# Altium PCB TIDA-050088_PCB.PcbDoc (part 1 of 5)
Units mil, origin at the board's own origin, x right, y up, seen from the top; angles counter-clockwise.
Board outline 8500 x 7000 mil, 8 copper layers (Top Layer, Layer 1 - GND, Signal Layer 2, Layer 3 - GND, Layer 4 - Power, Signal Layer 5, Layer 6 - GND, Bottom Layer), stack 61.6 mil thick; 537 components, 169 nets, 1427 pads, 1411 vias.
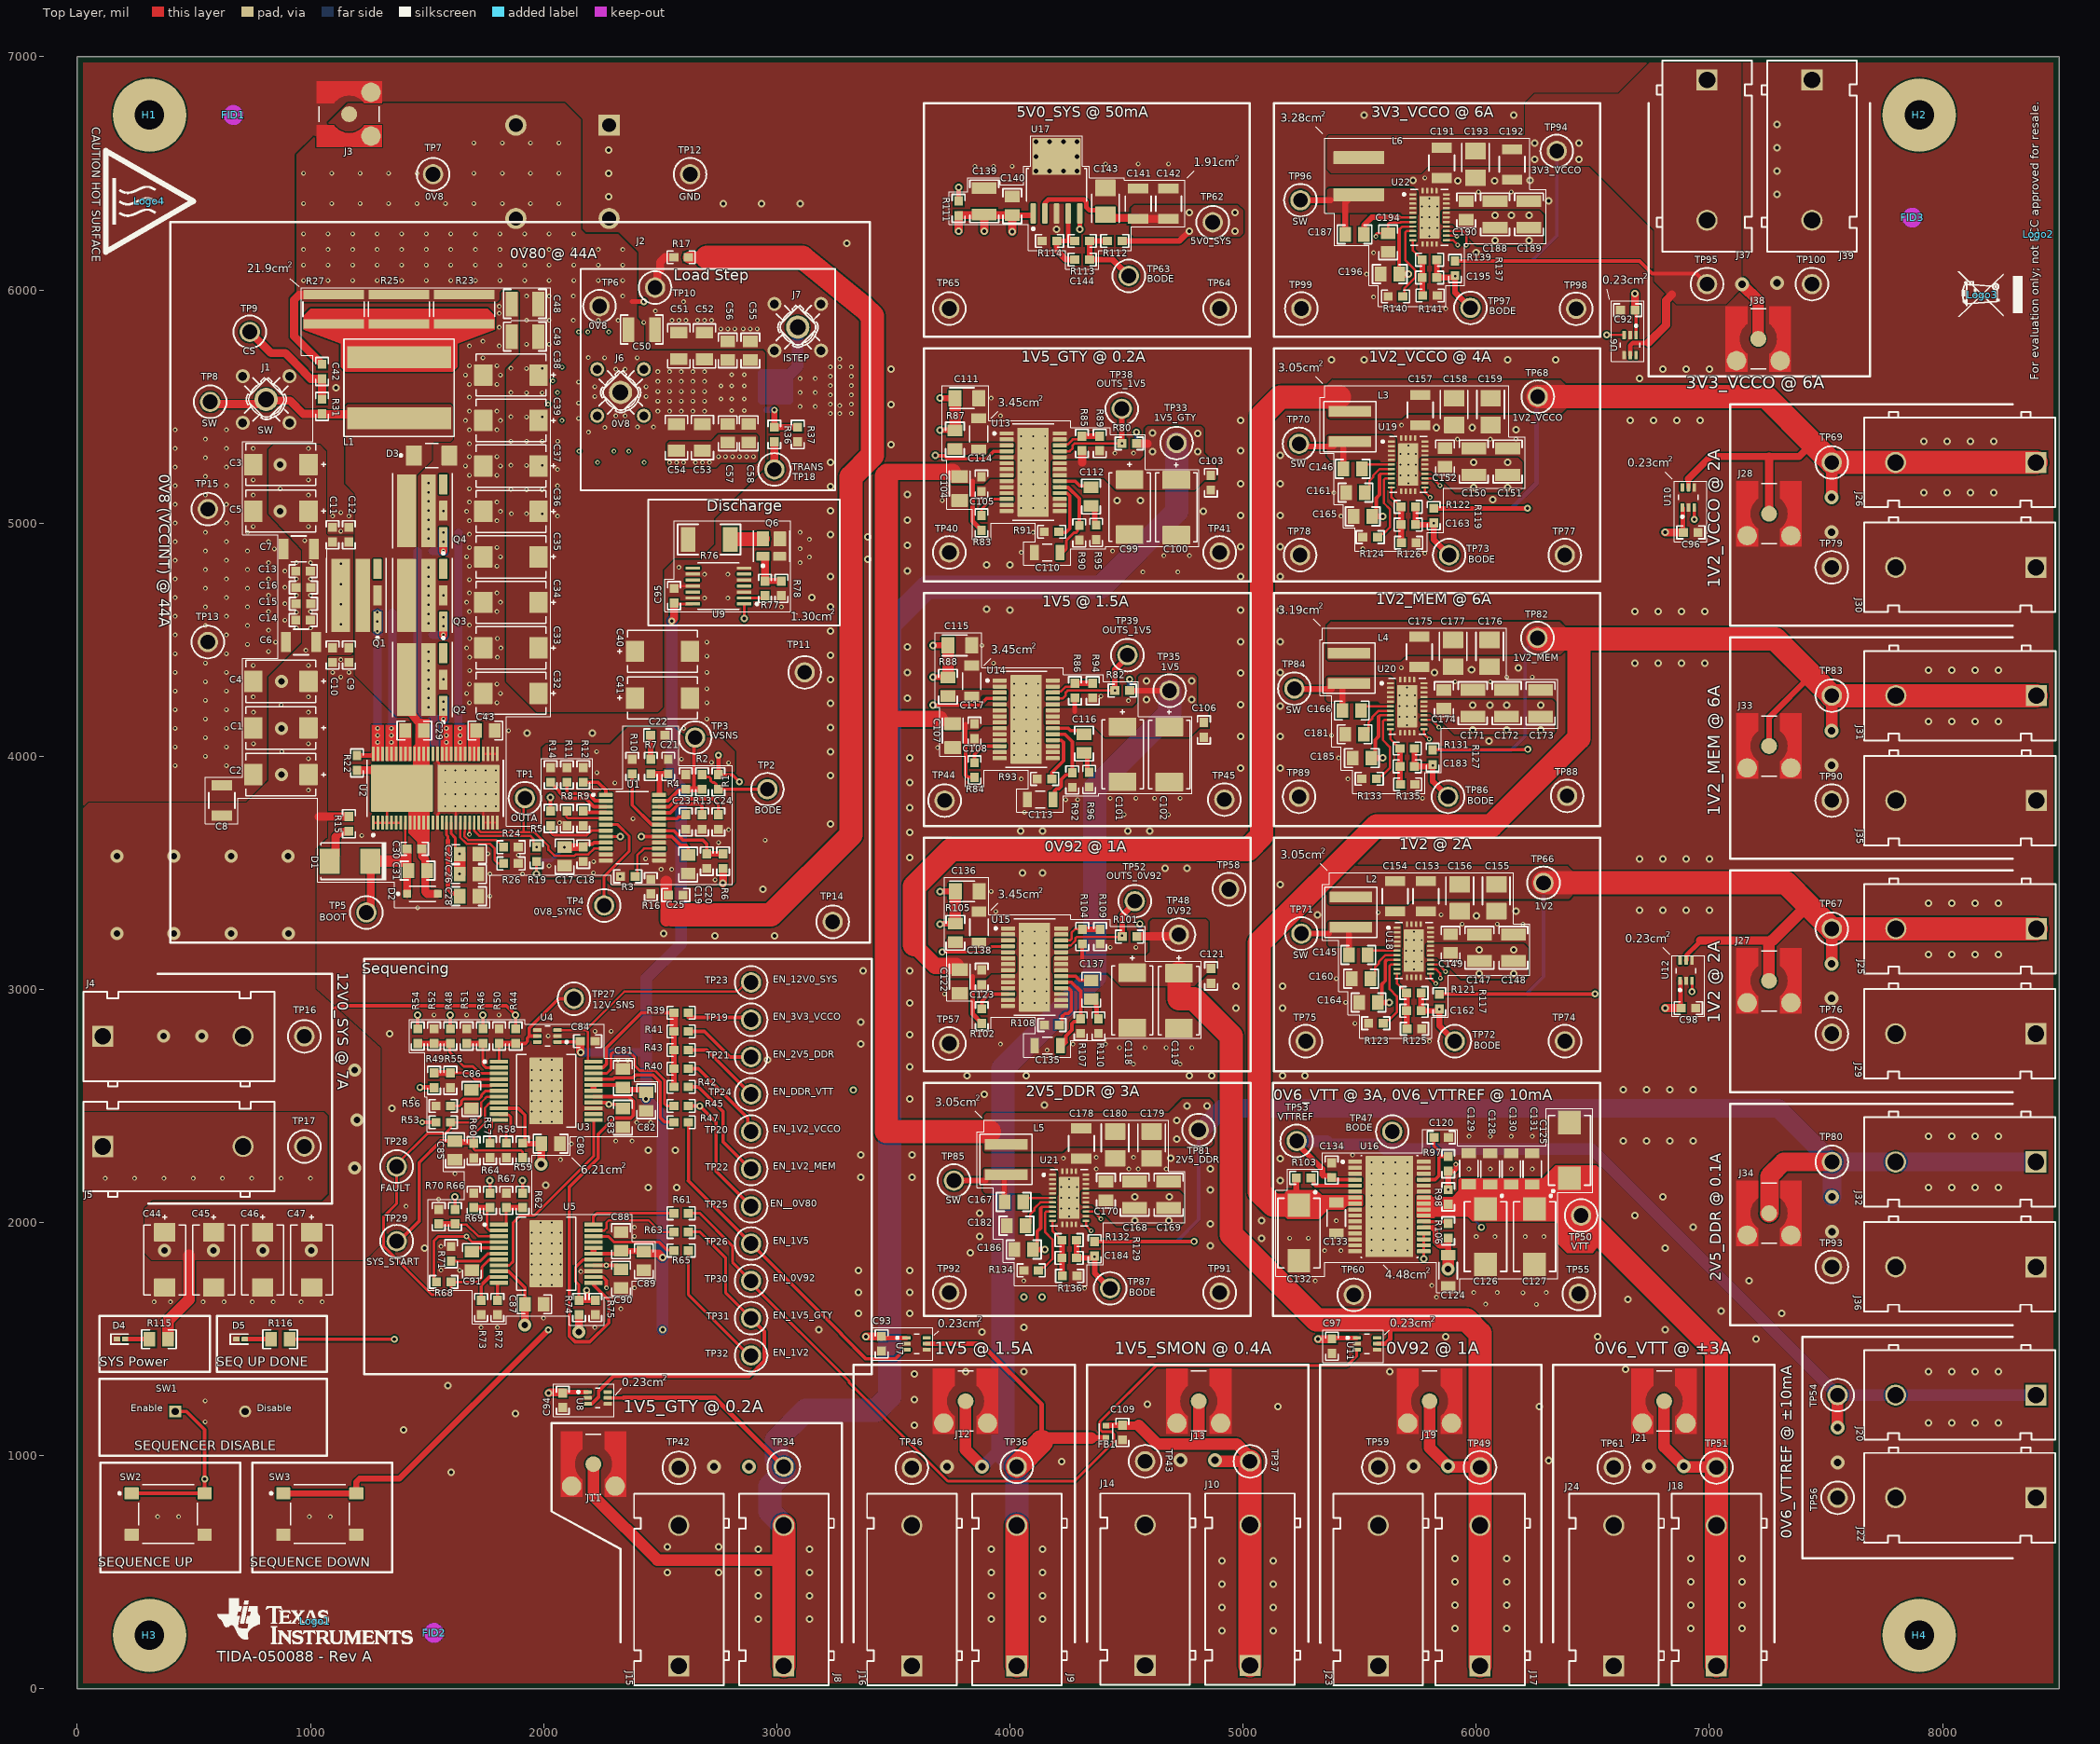
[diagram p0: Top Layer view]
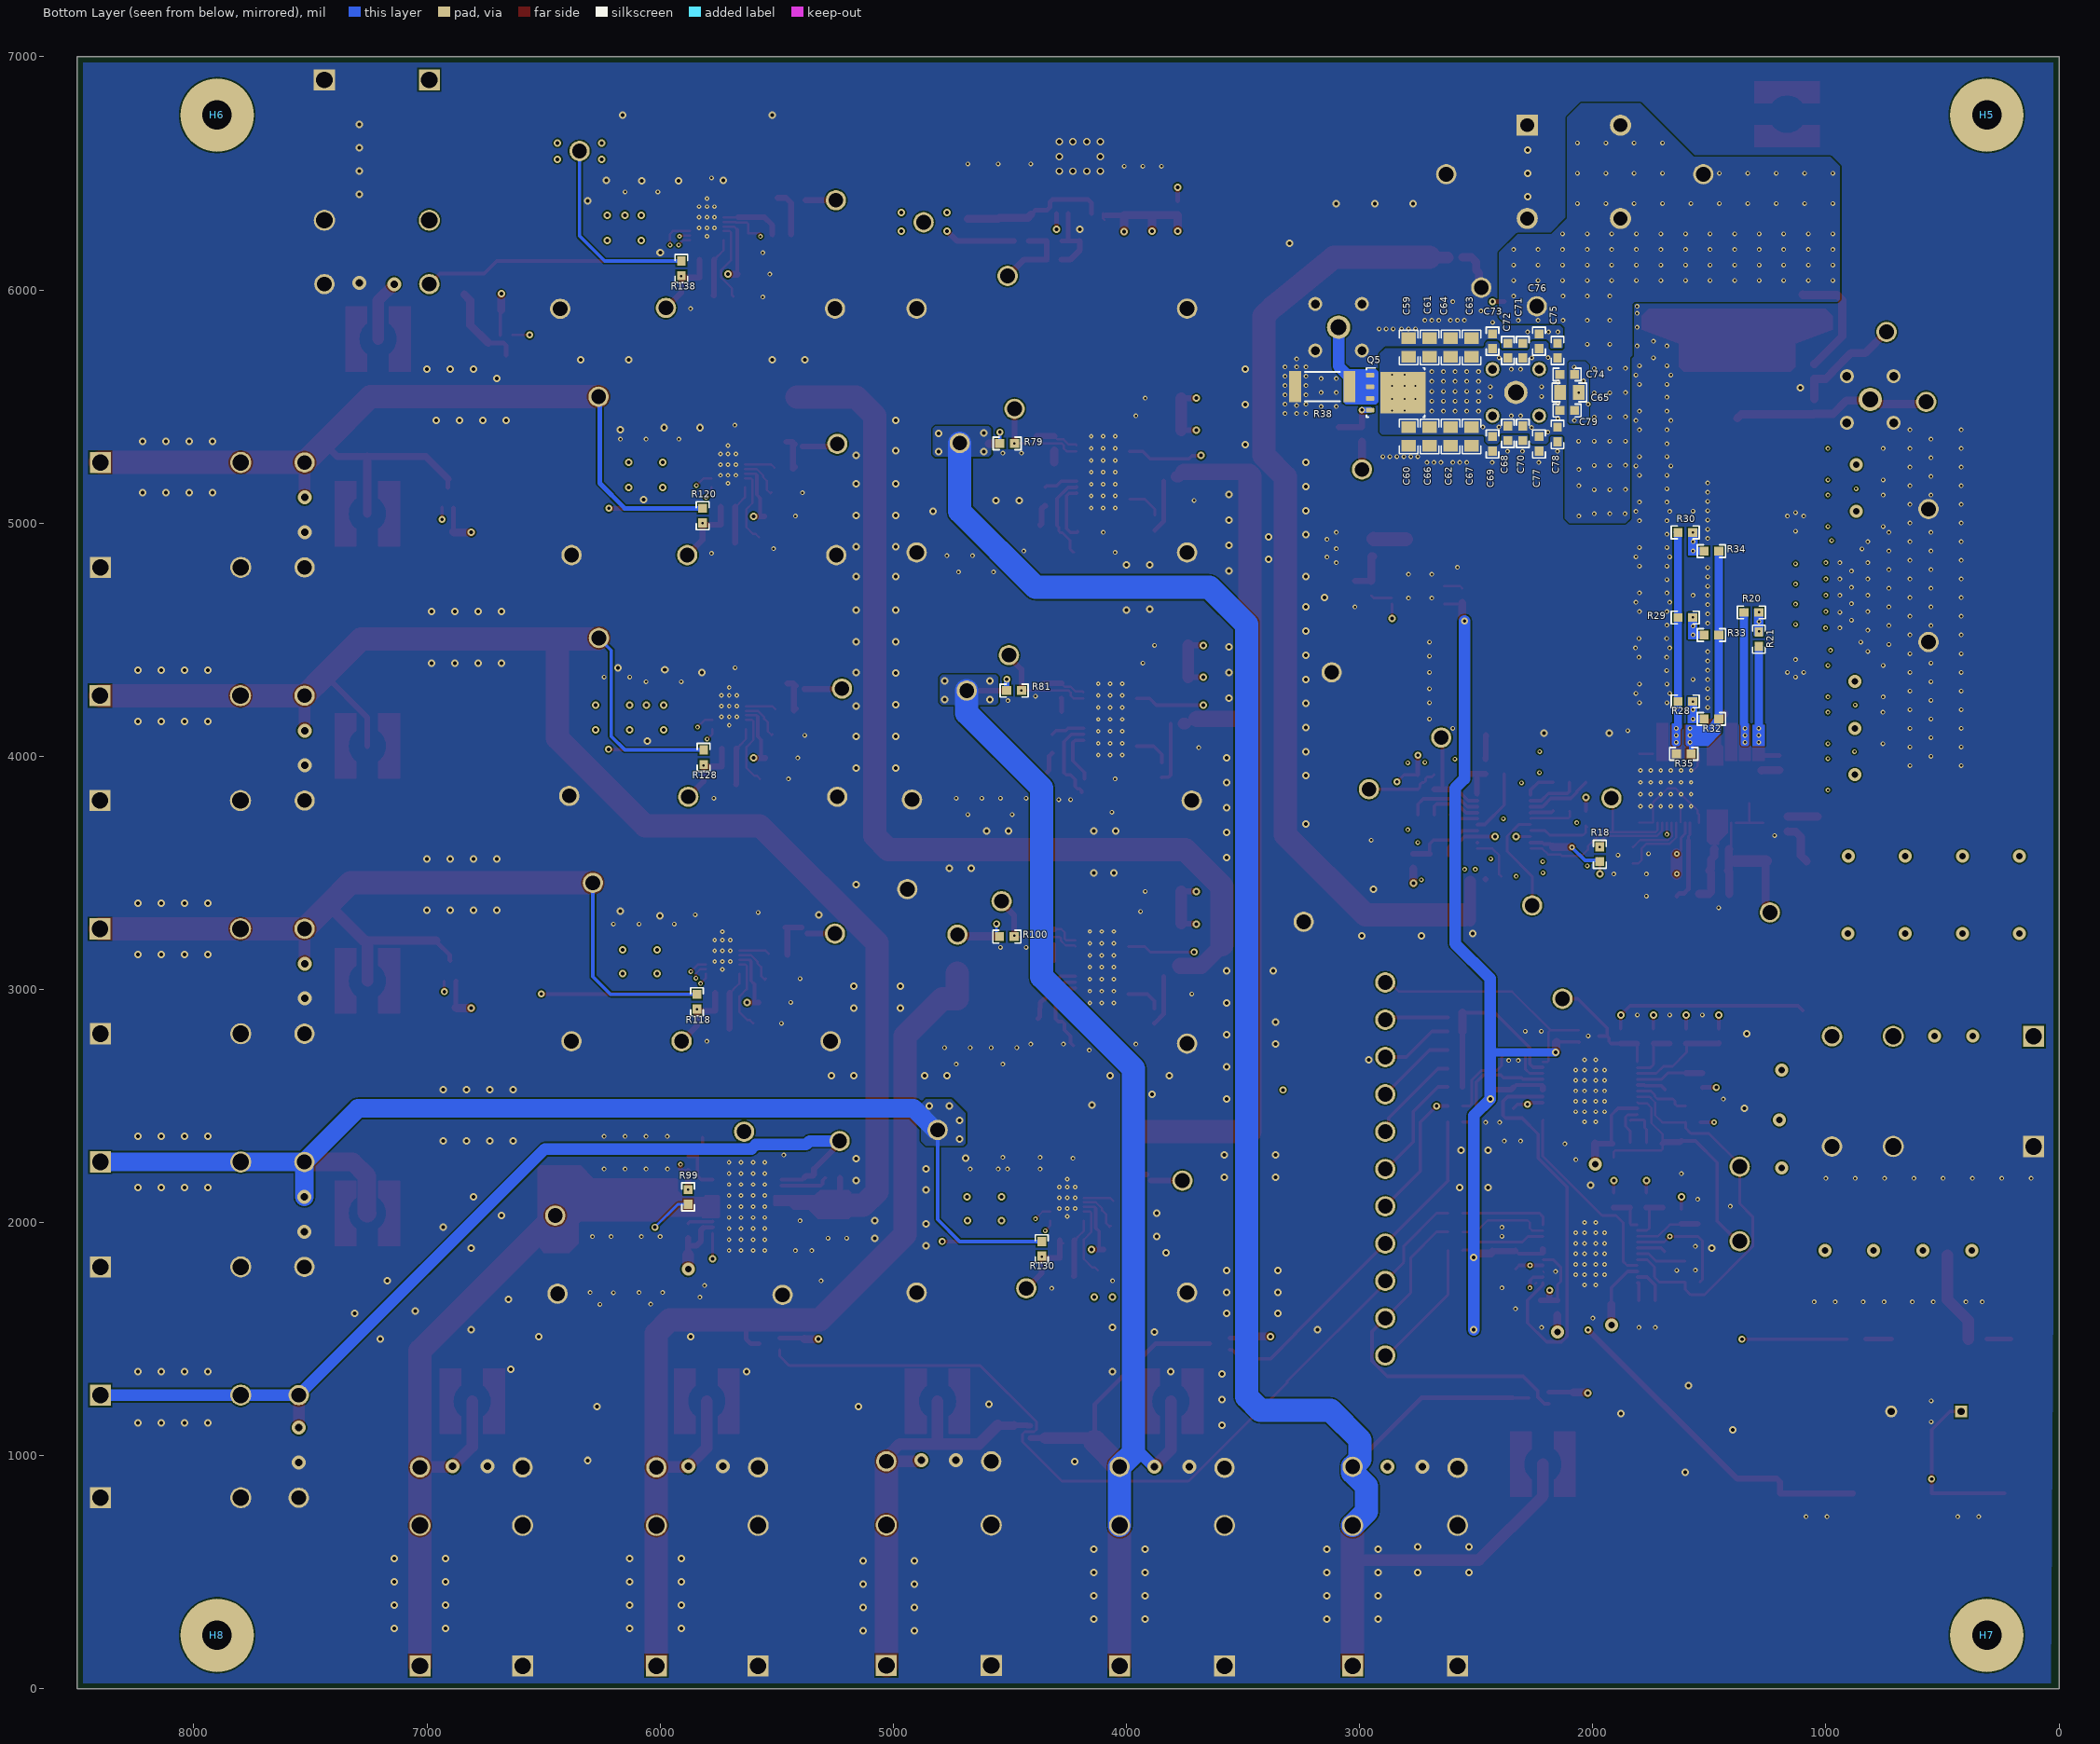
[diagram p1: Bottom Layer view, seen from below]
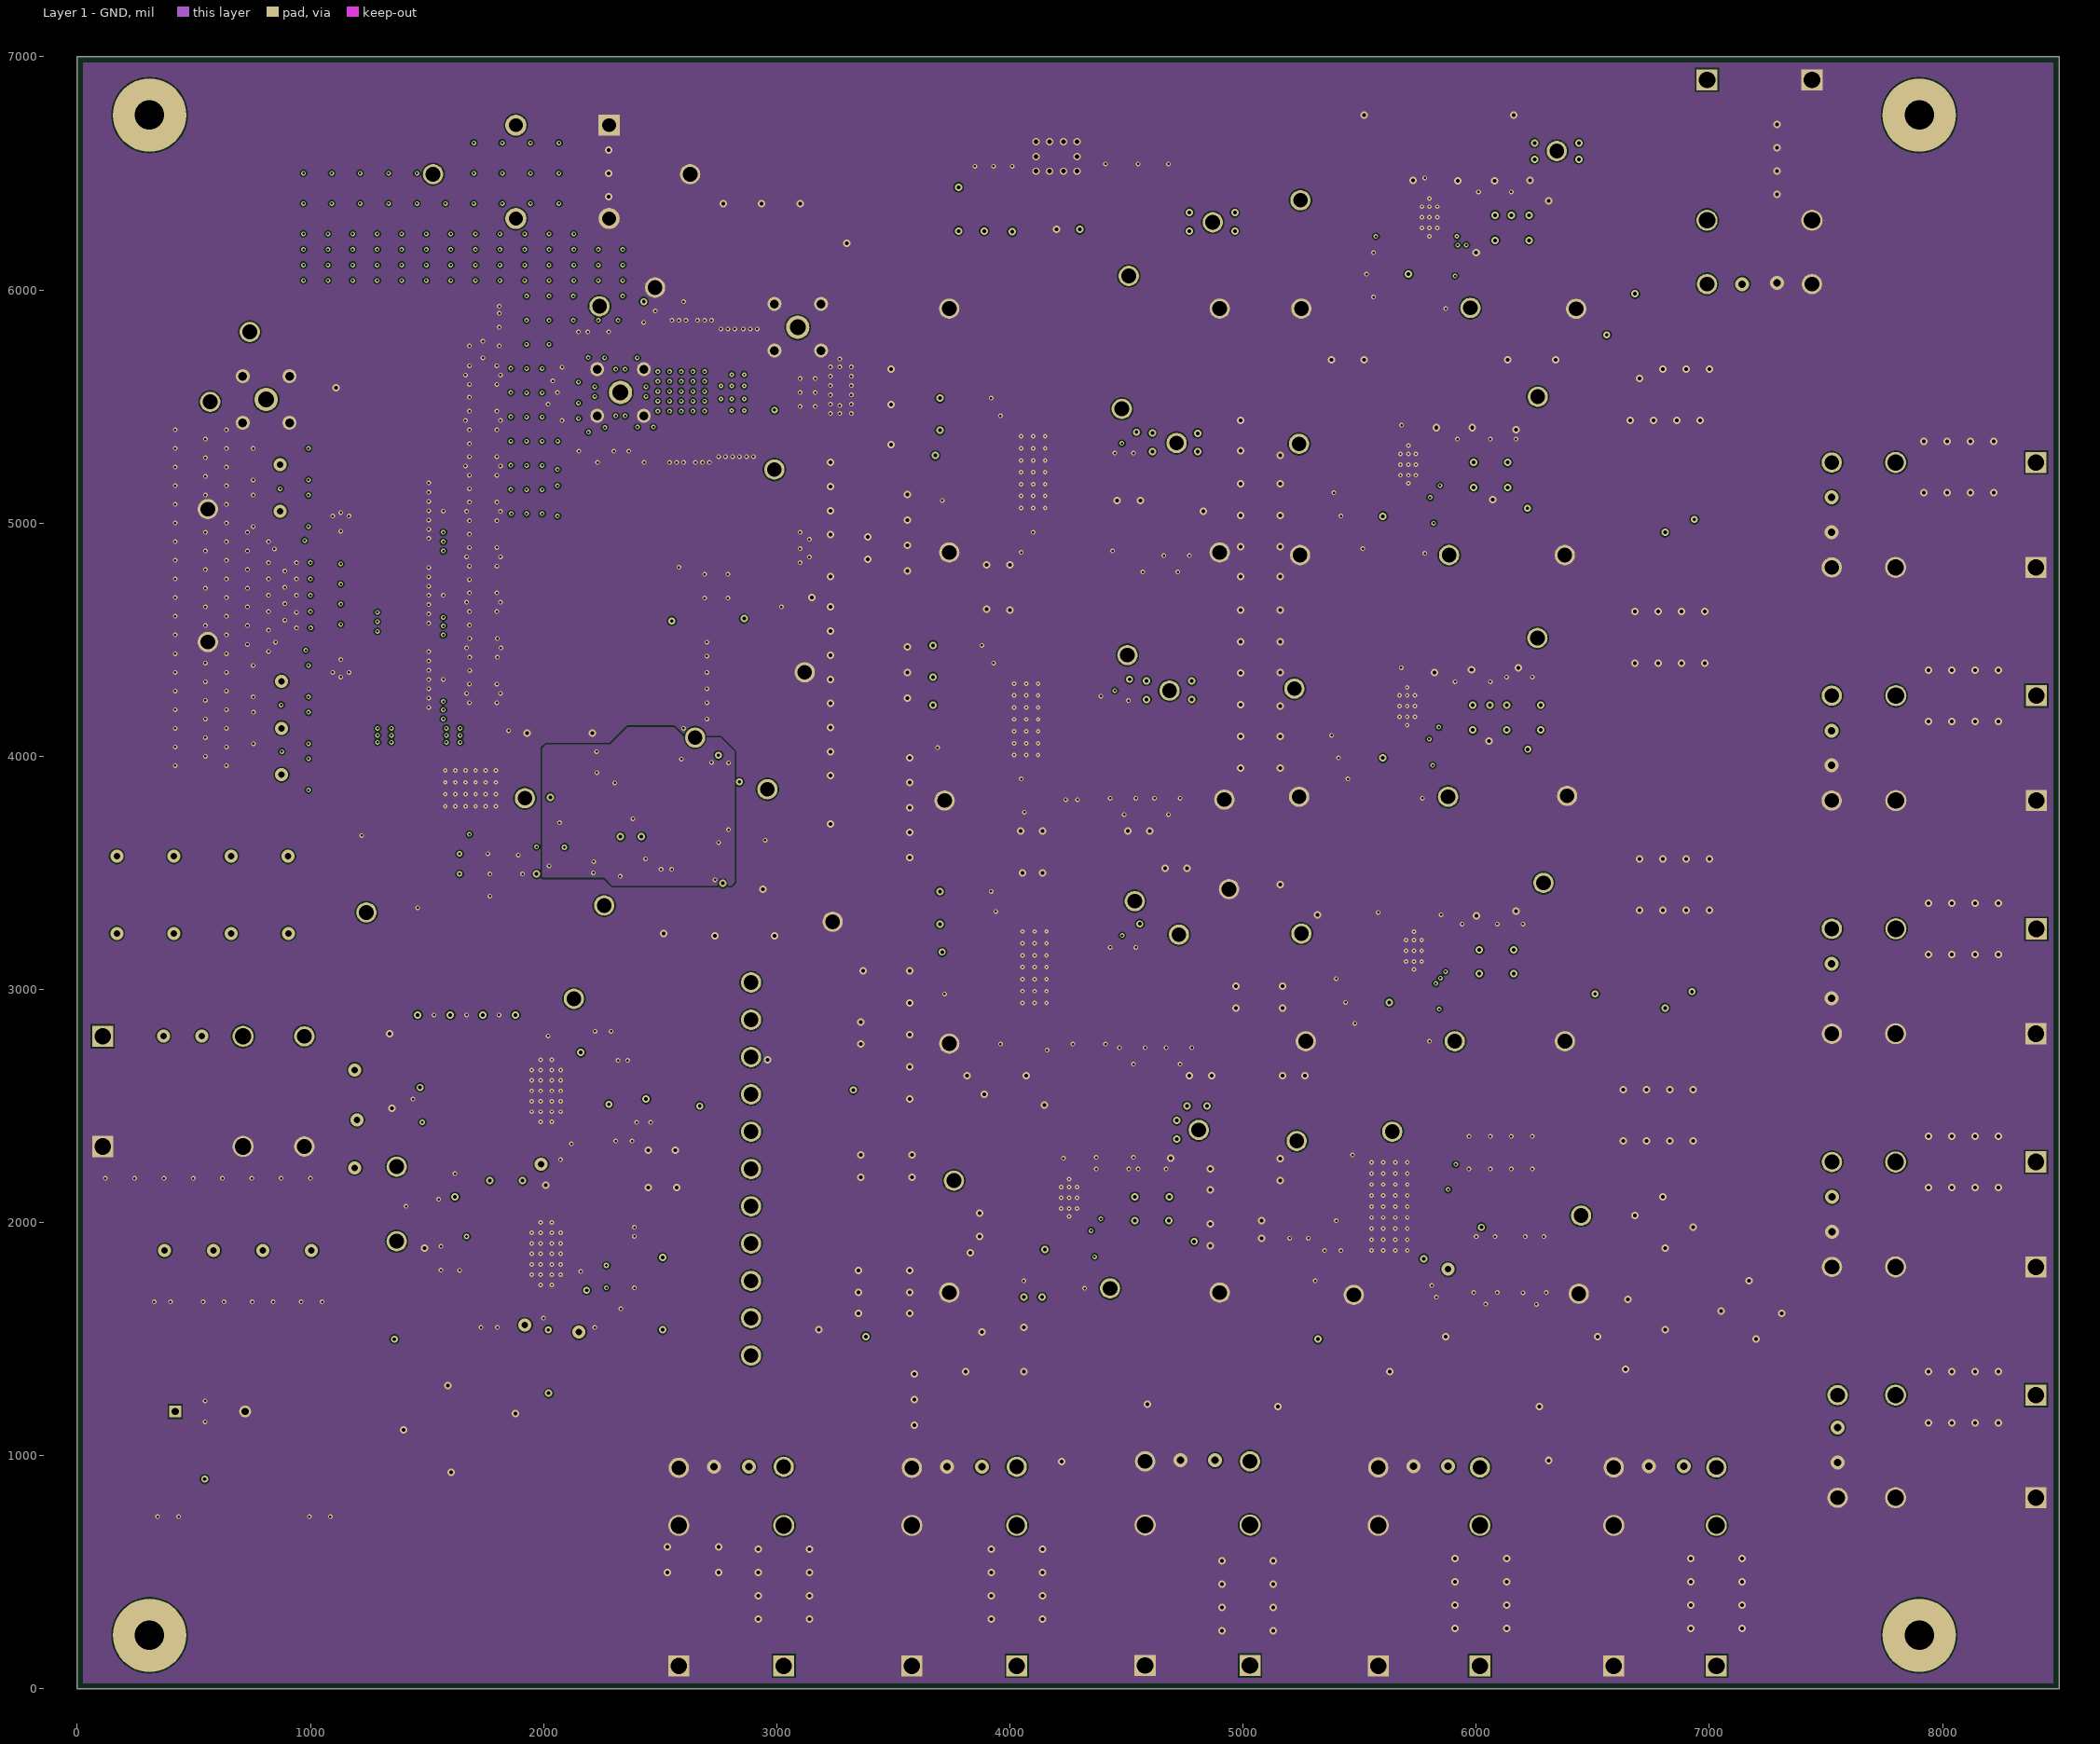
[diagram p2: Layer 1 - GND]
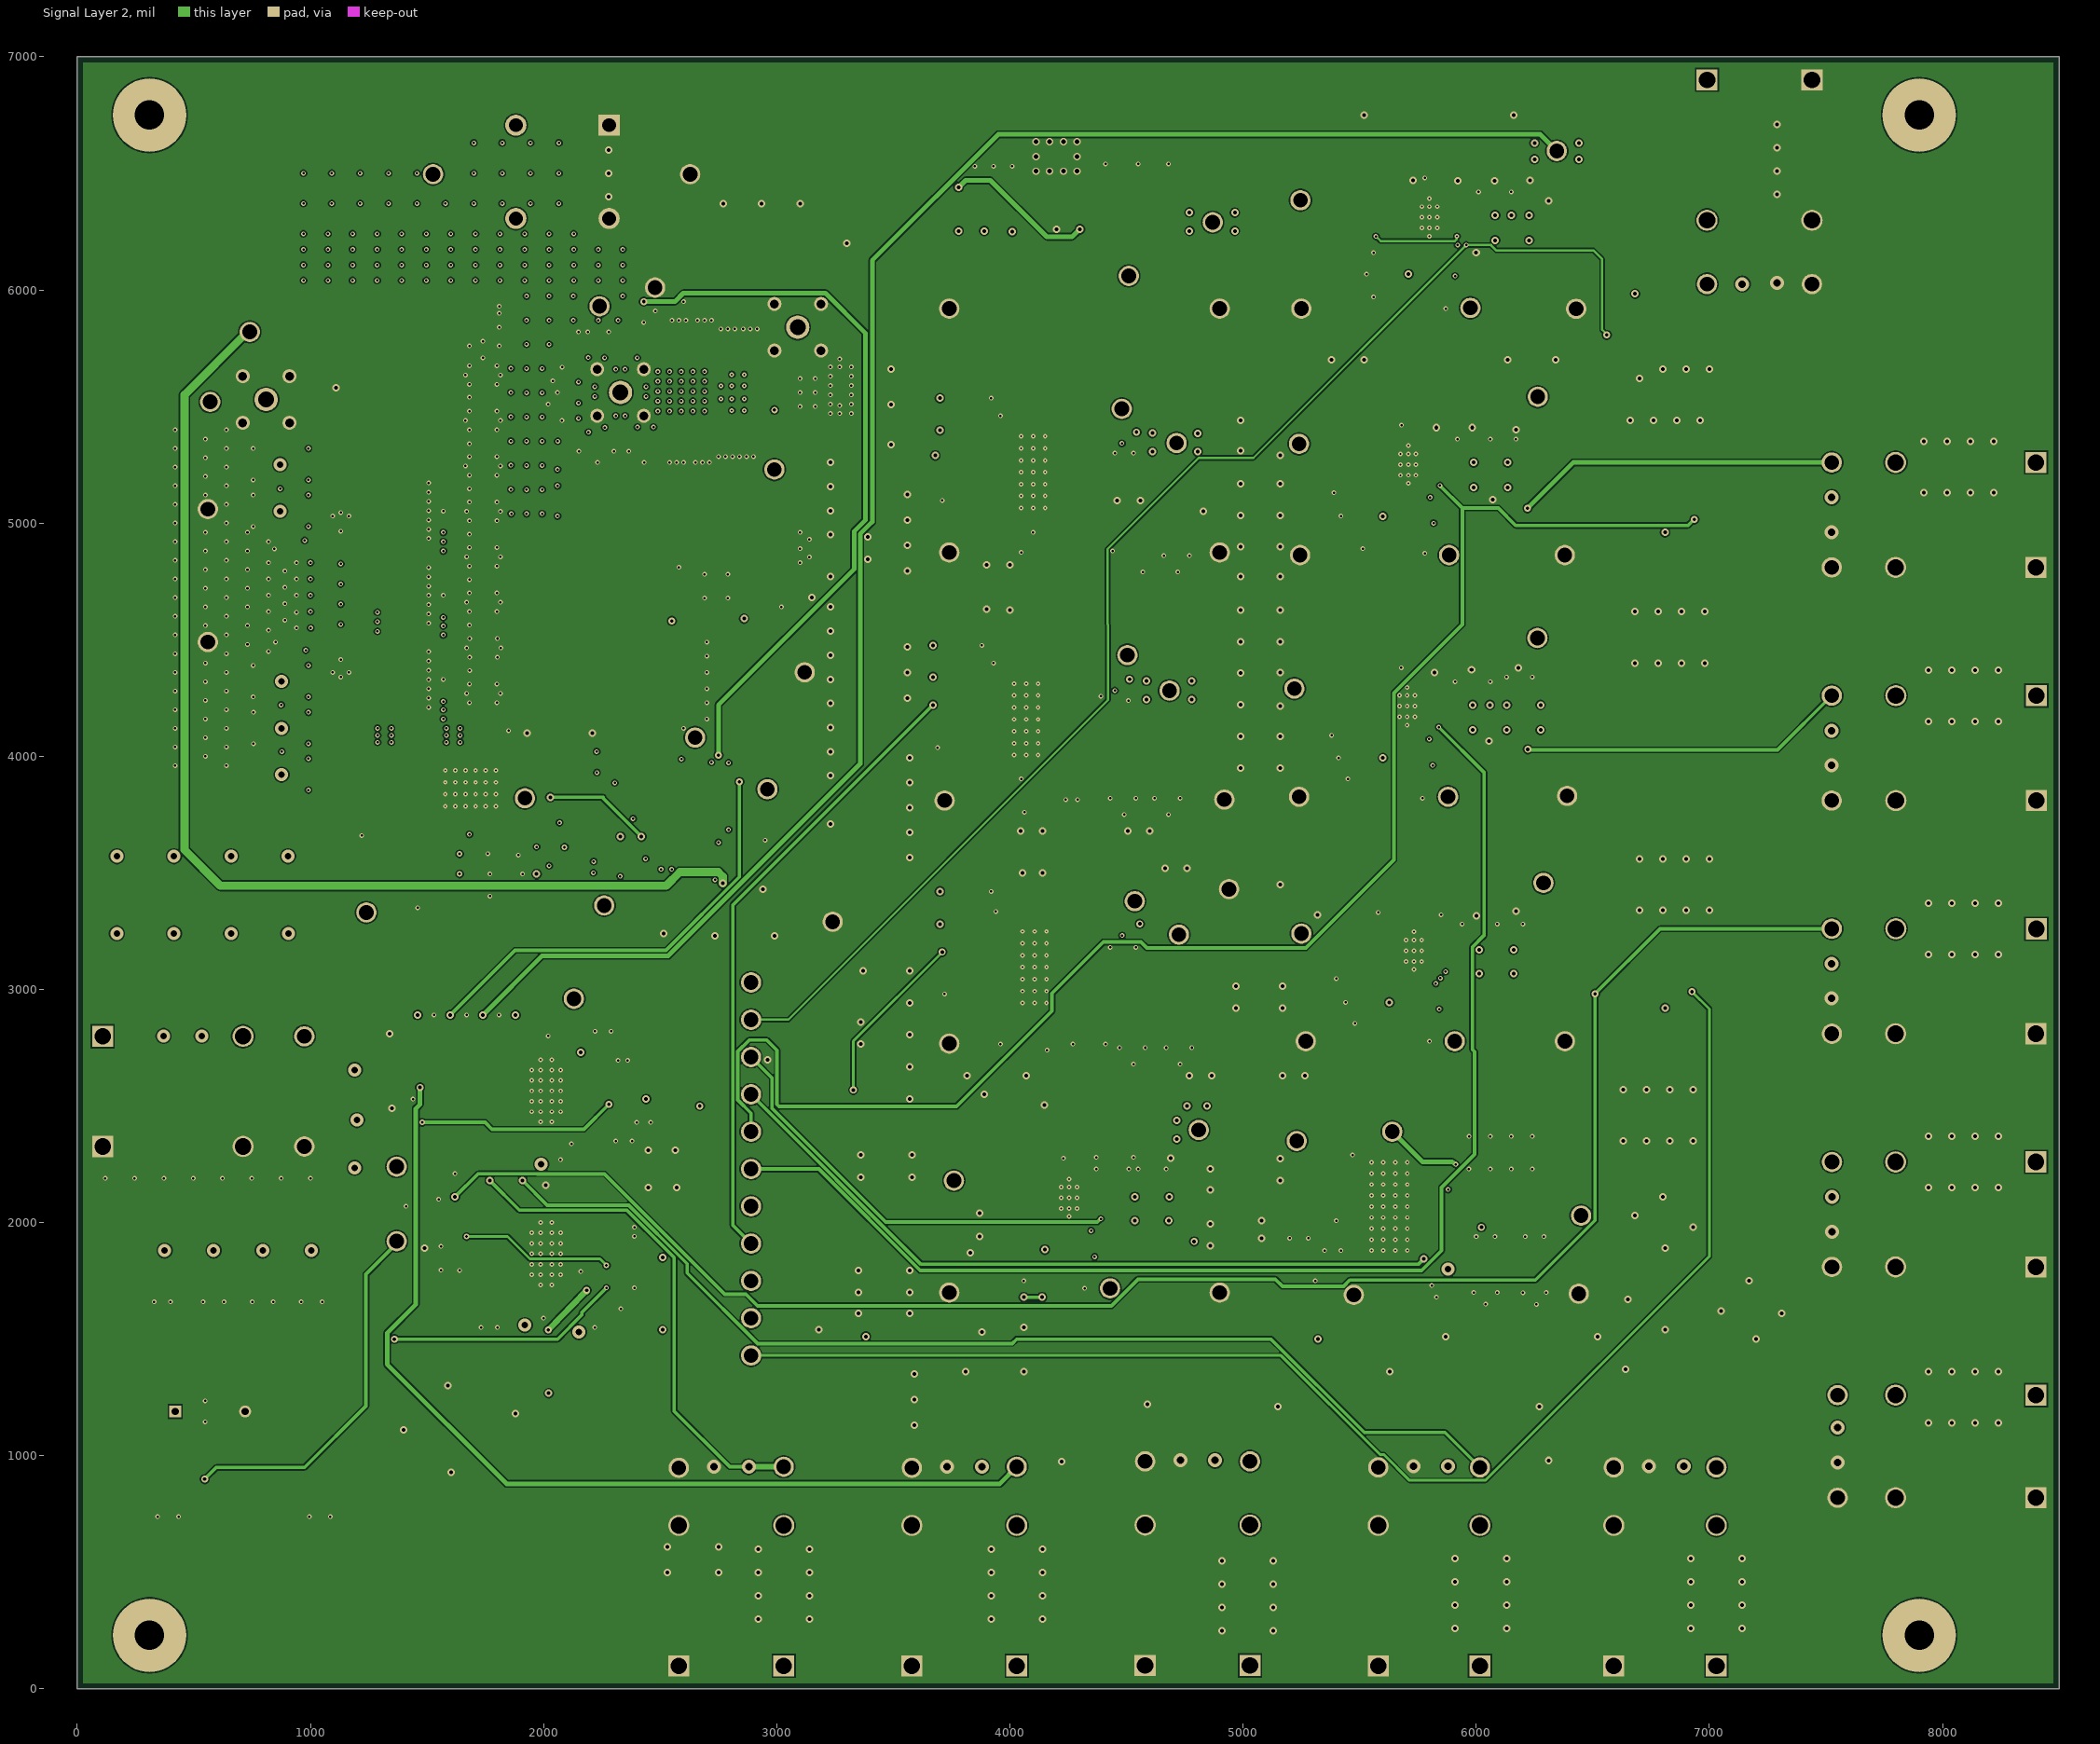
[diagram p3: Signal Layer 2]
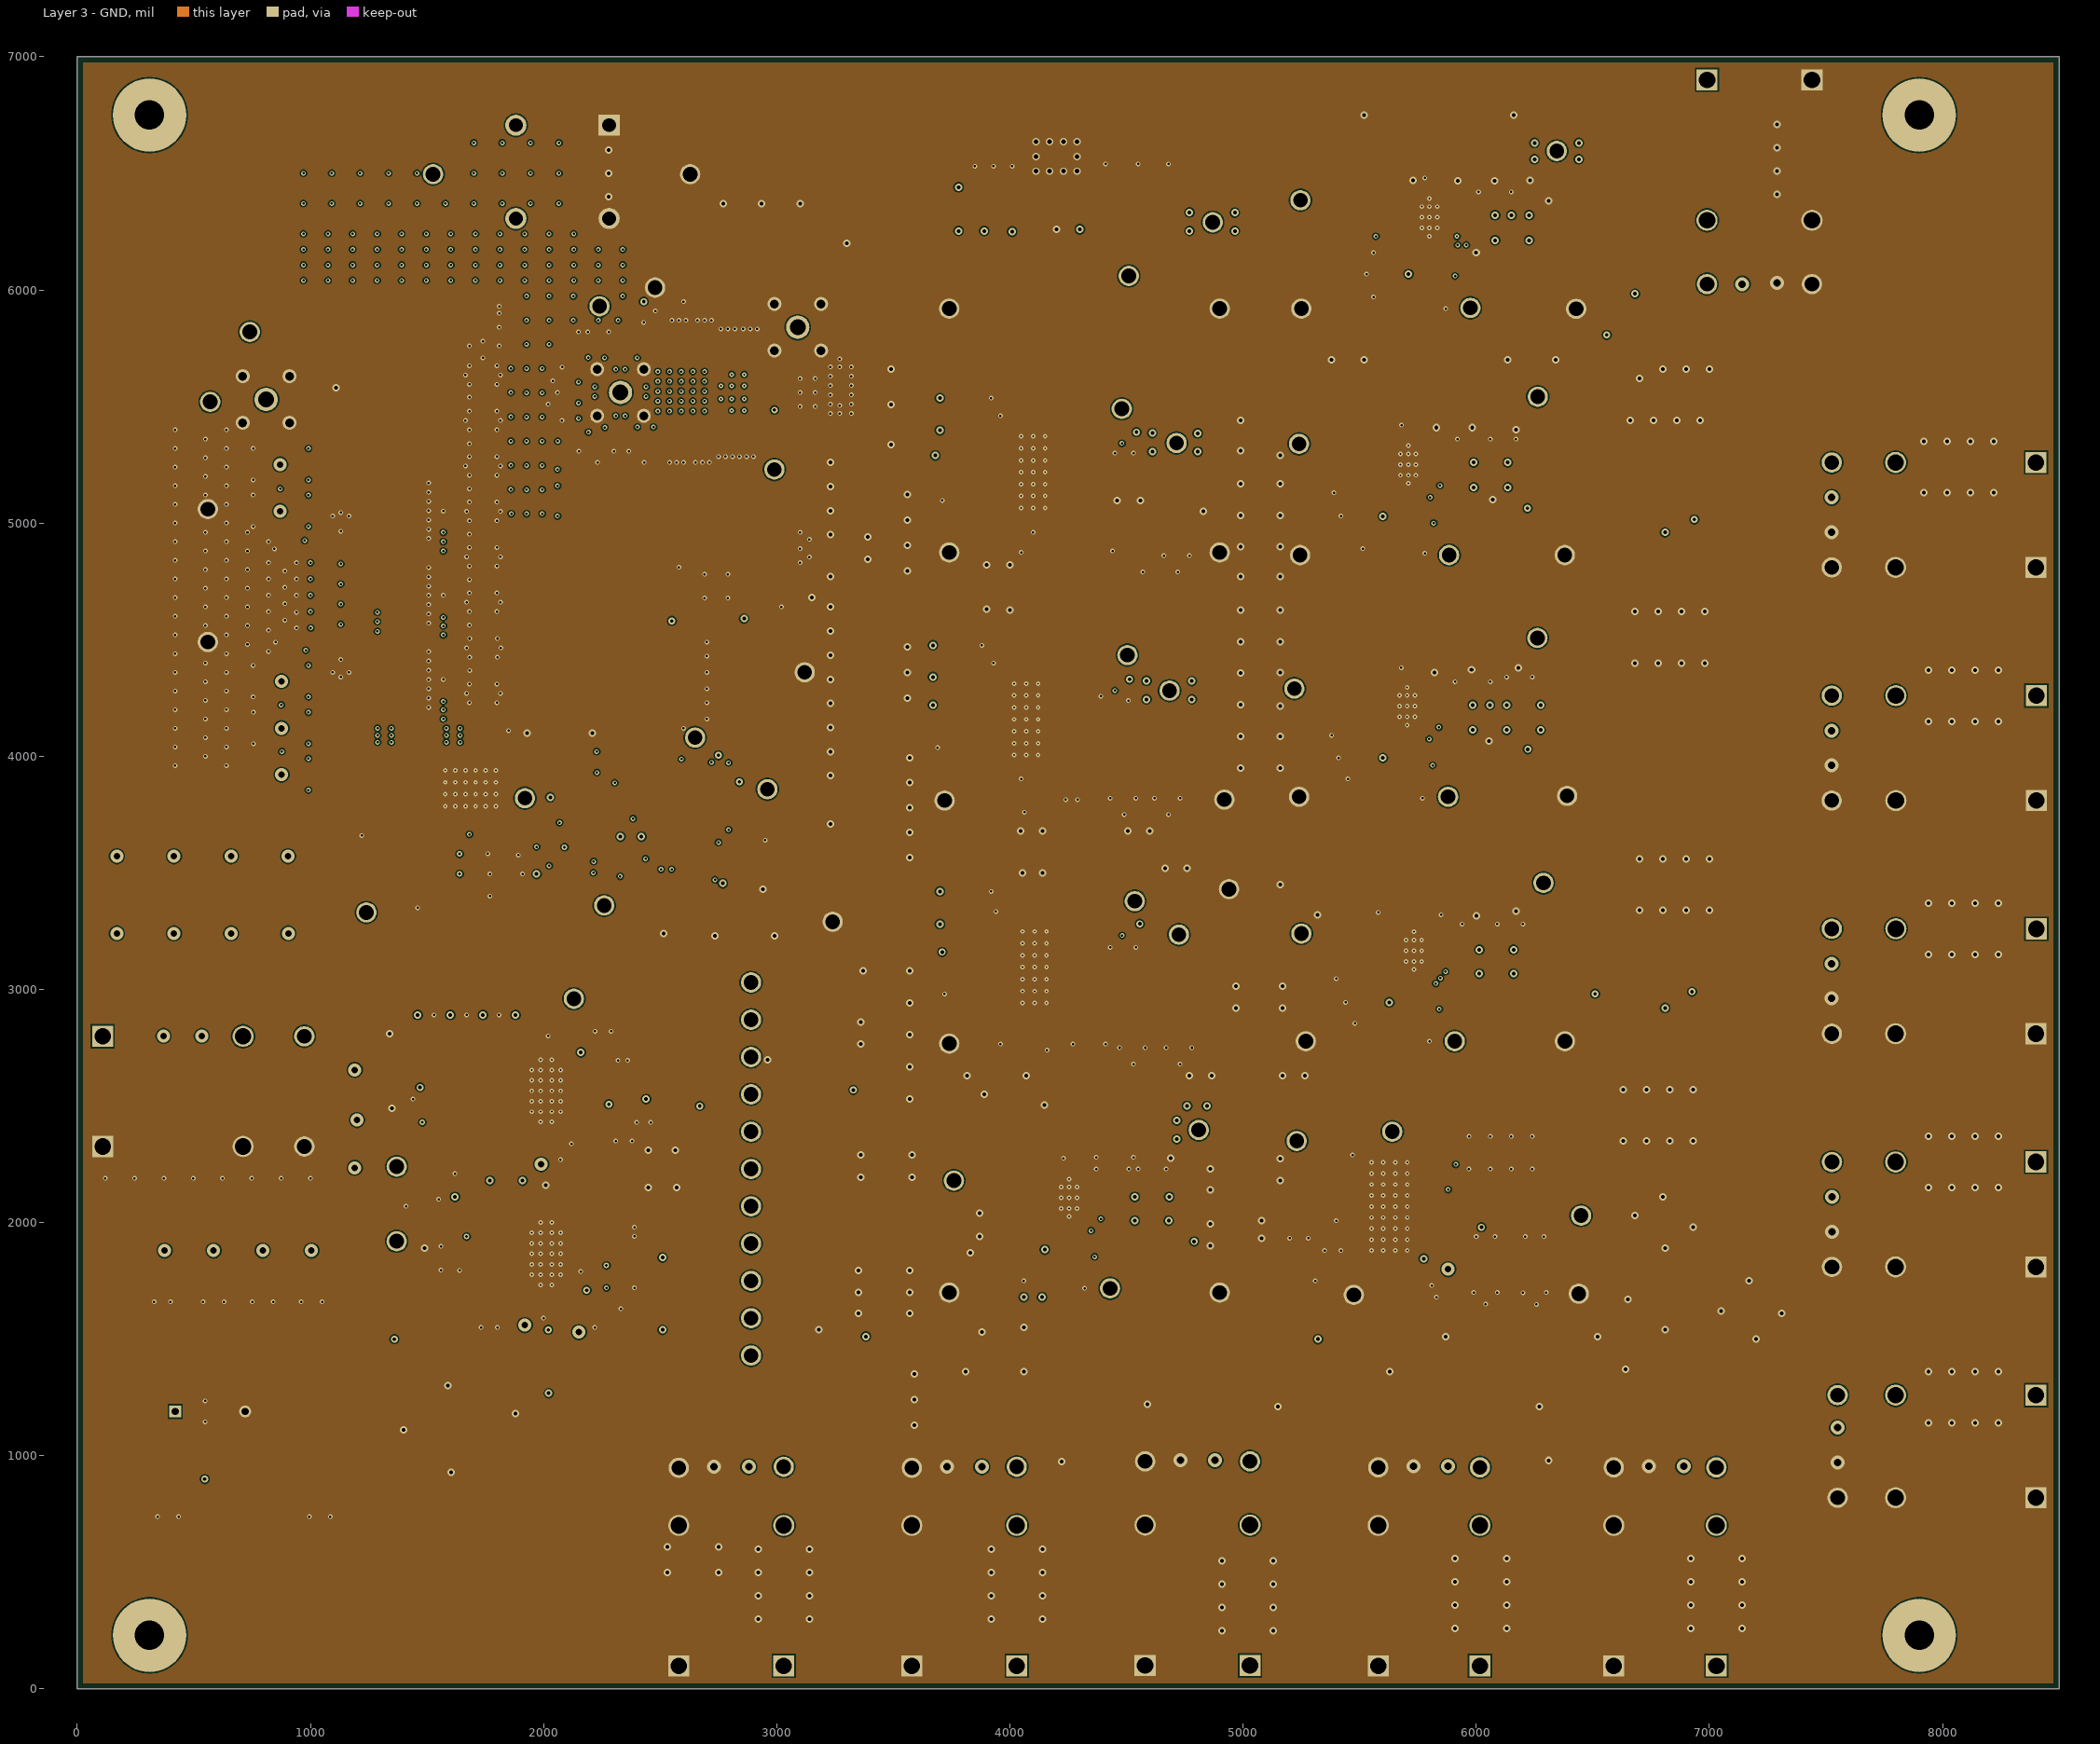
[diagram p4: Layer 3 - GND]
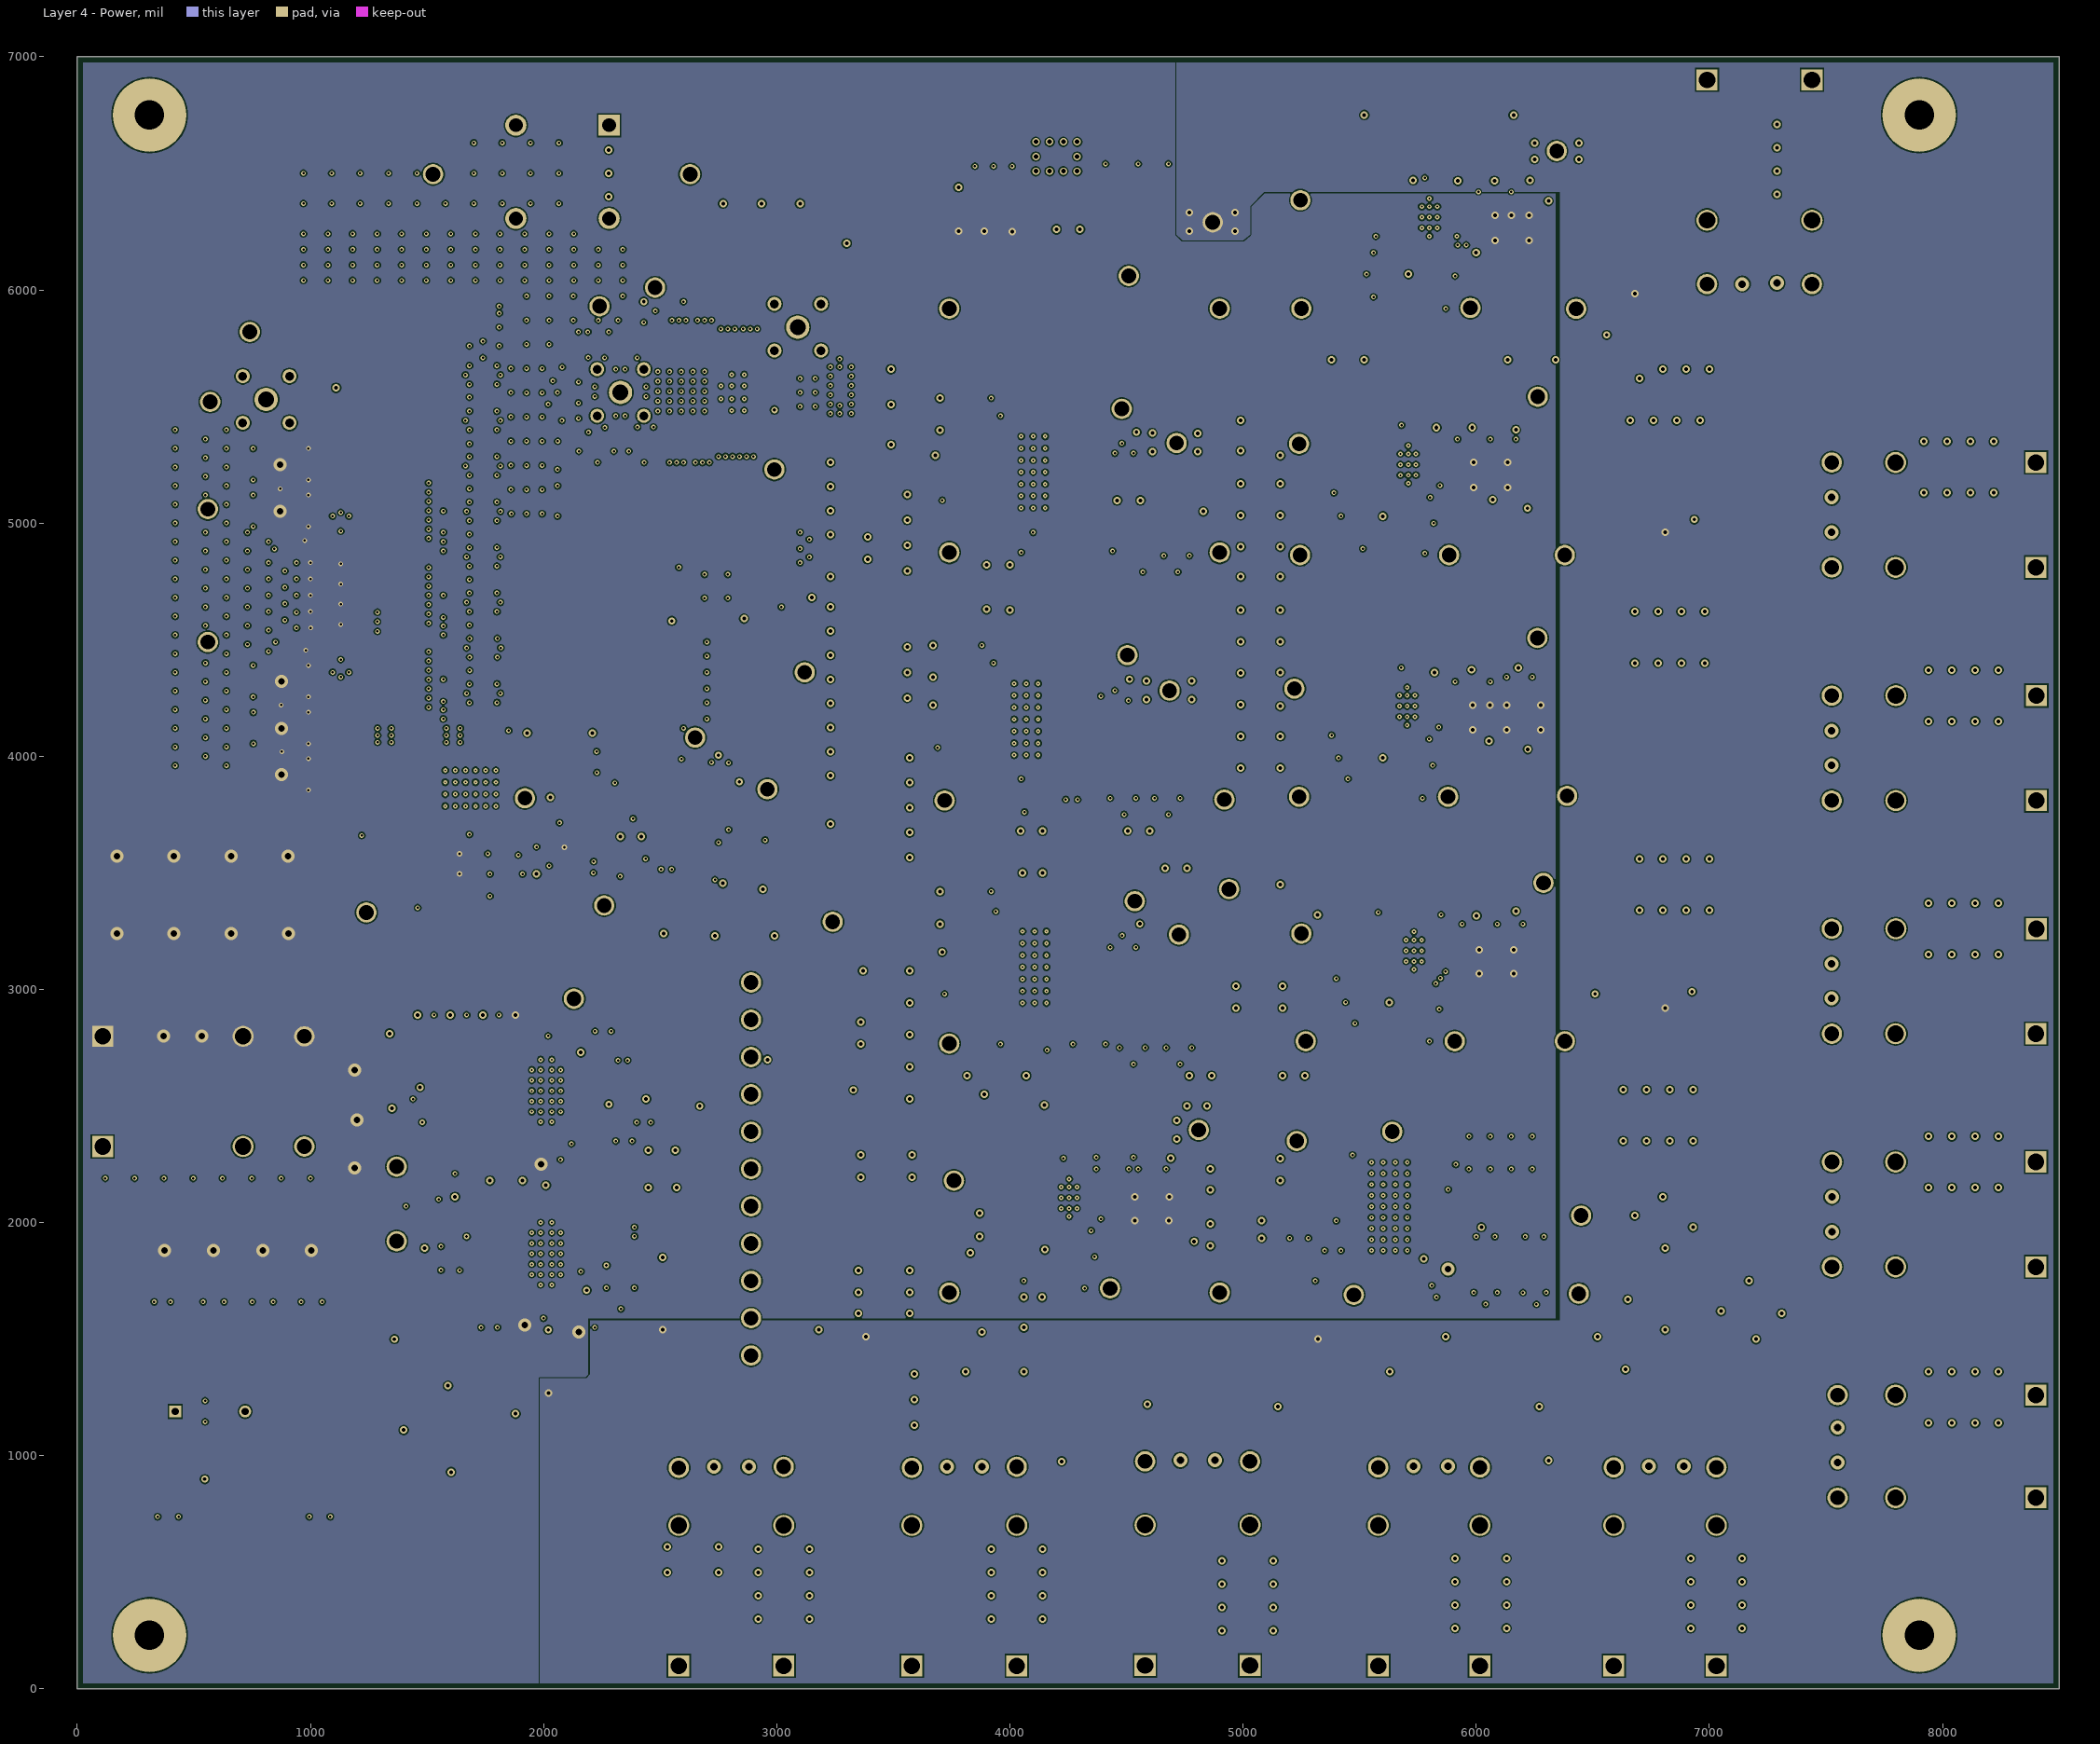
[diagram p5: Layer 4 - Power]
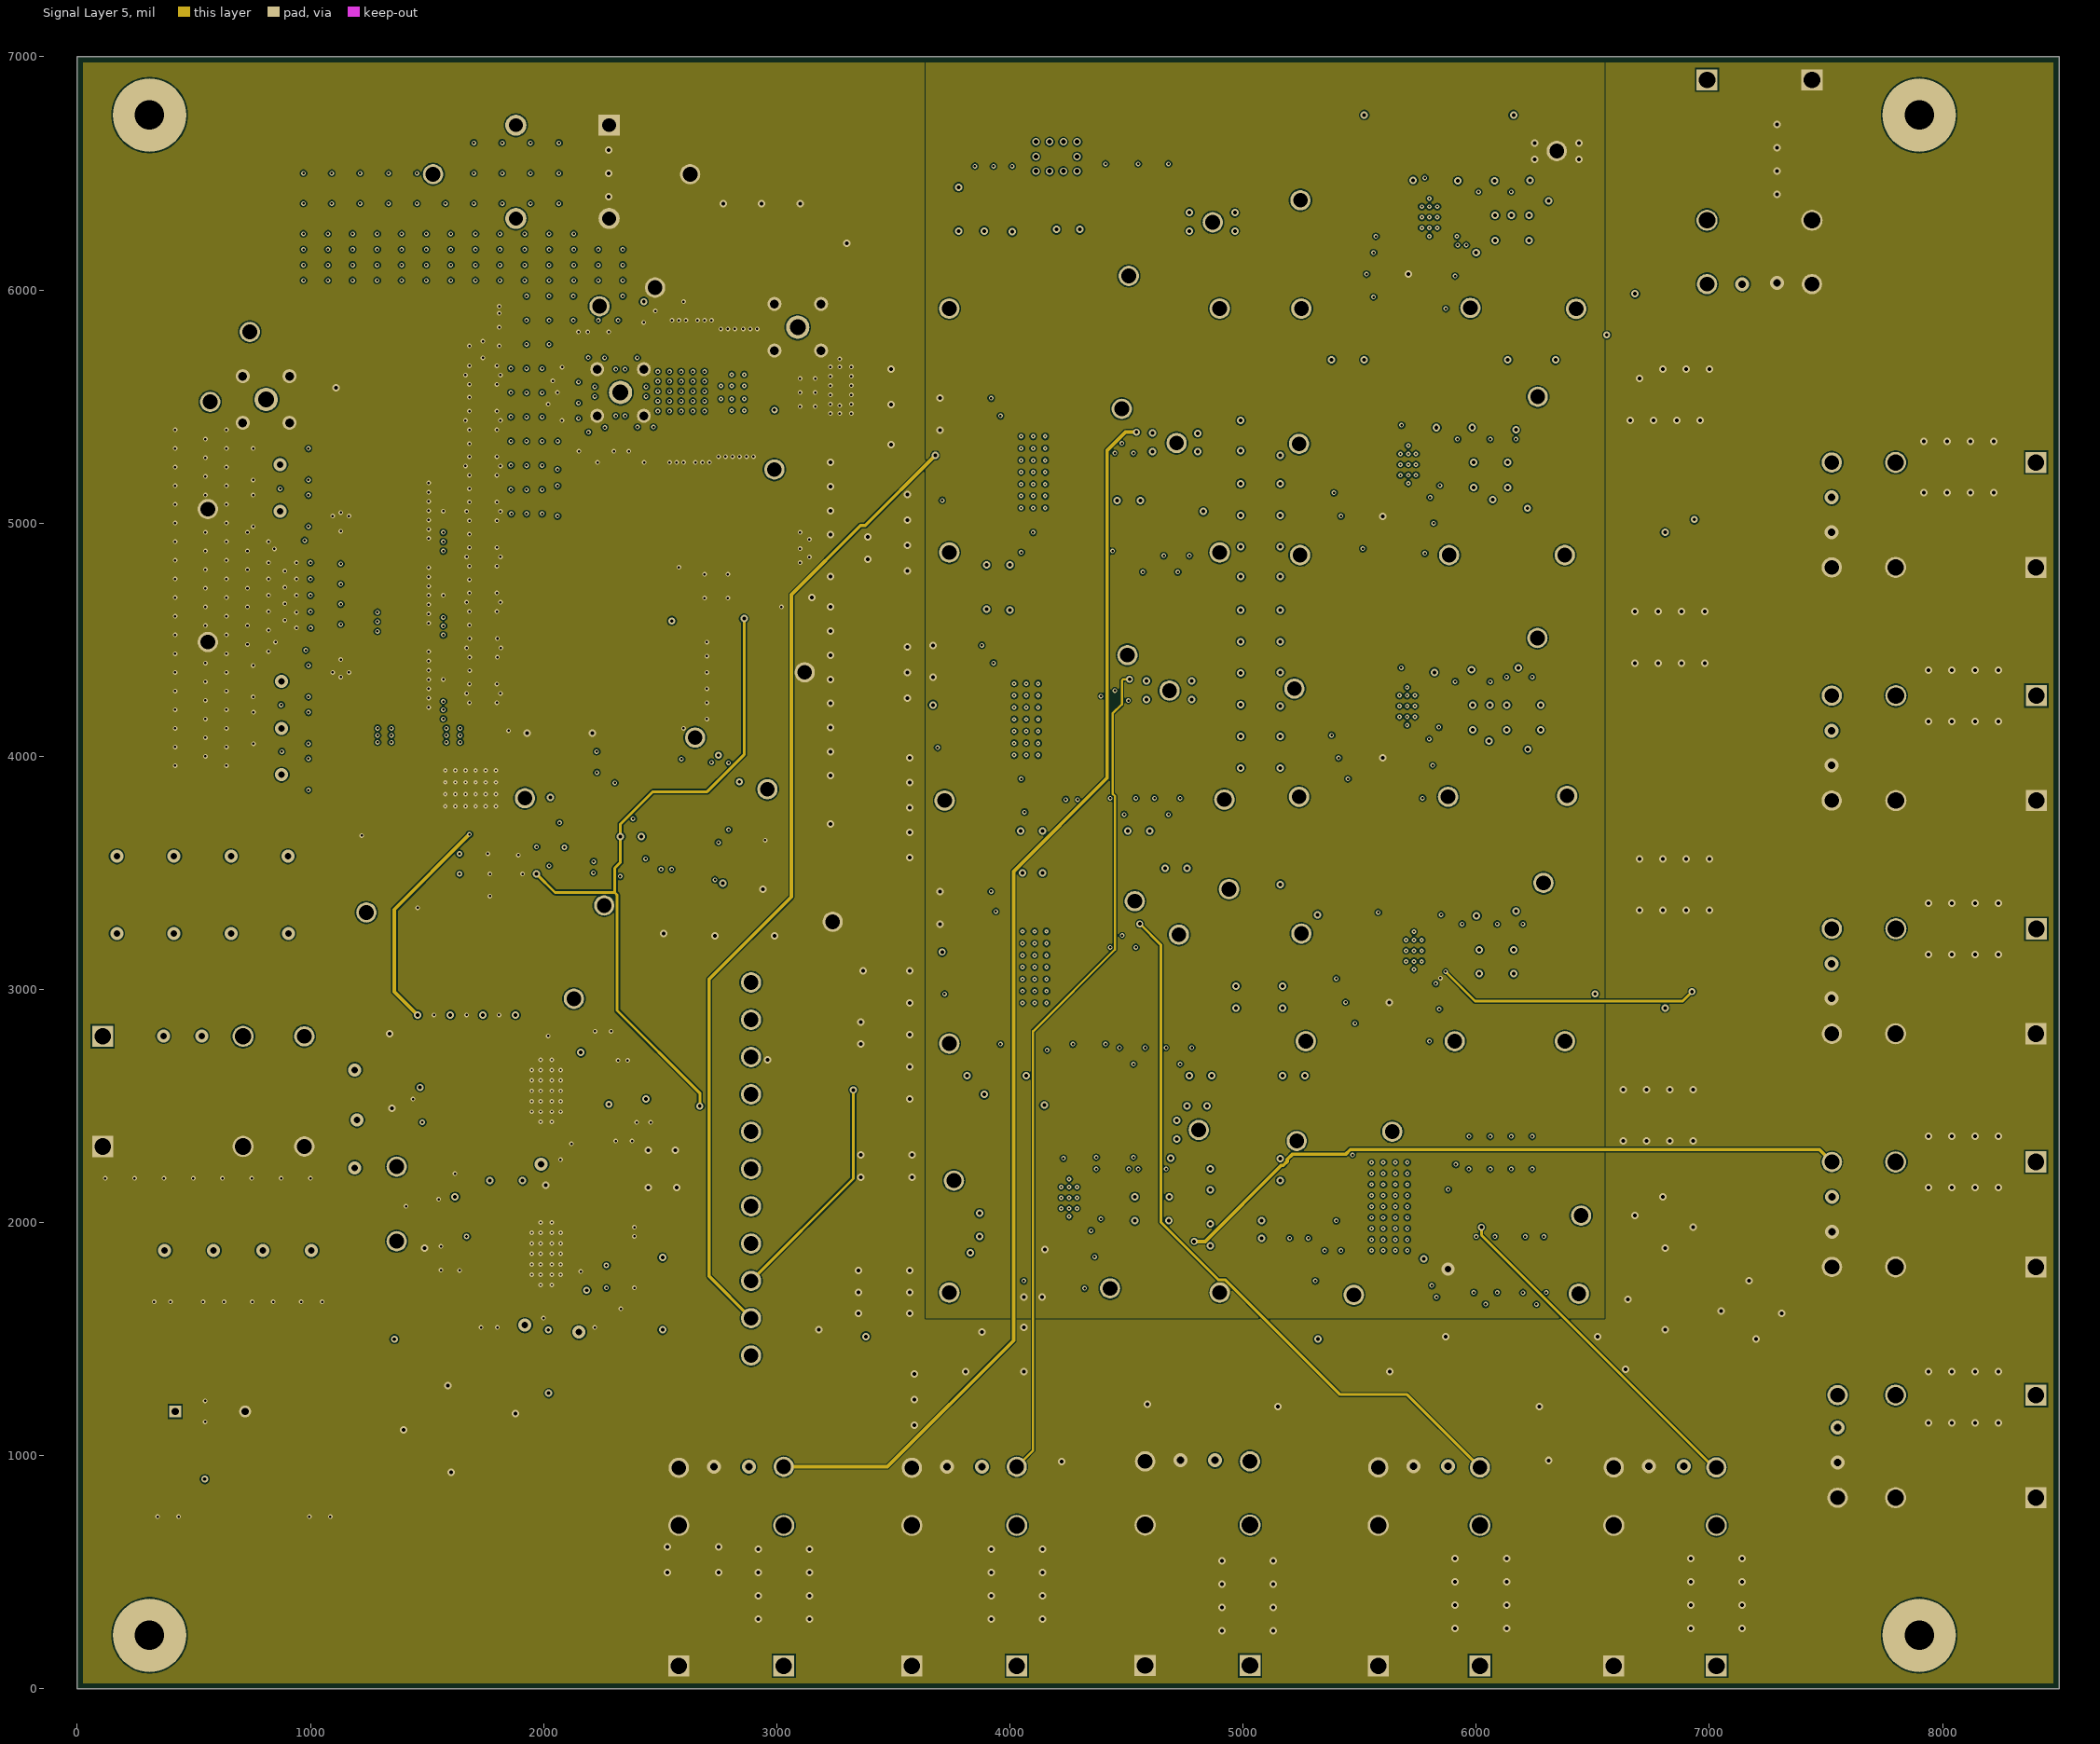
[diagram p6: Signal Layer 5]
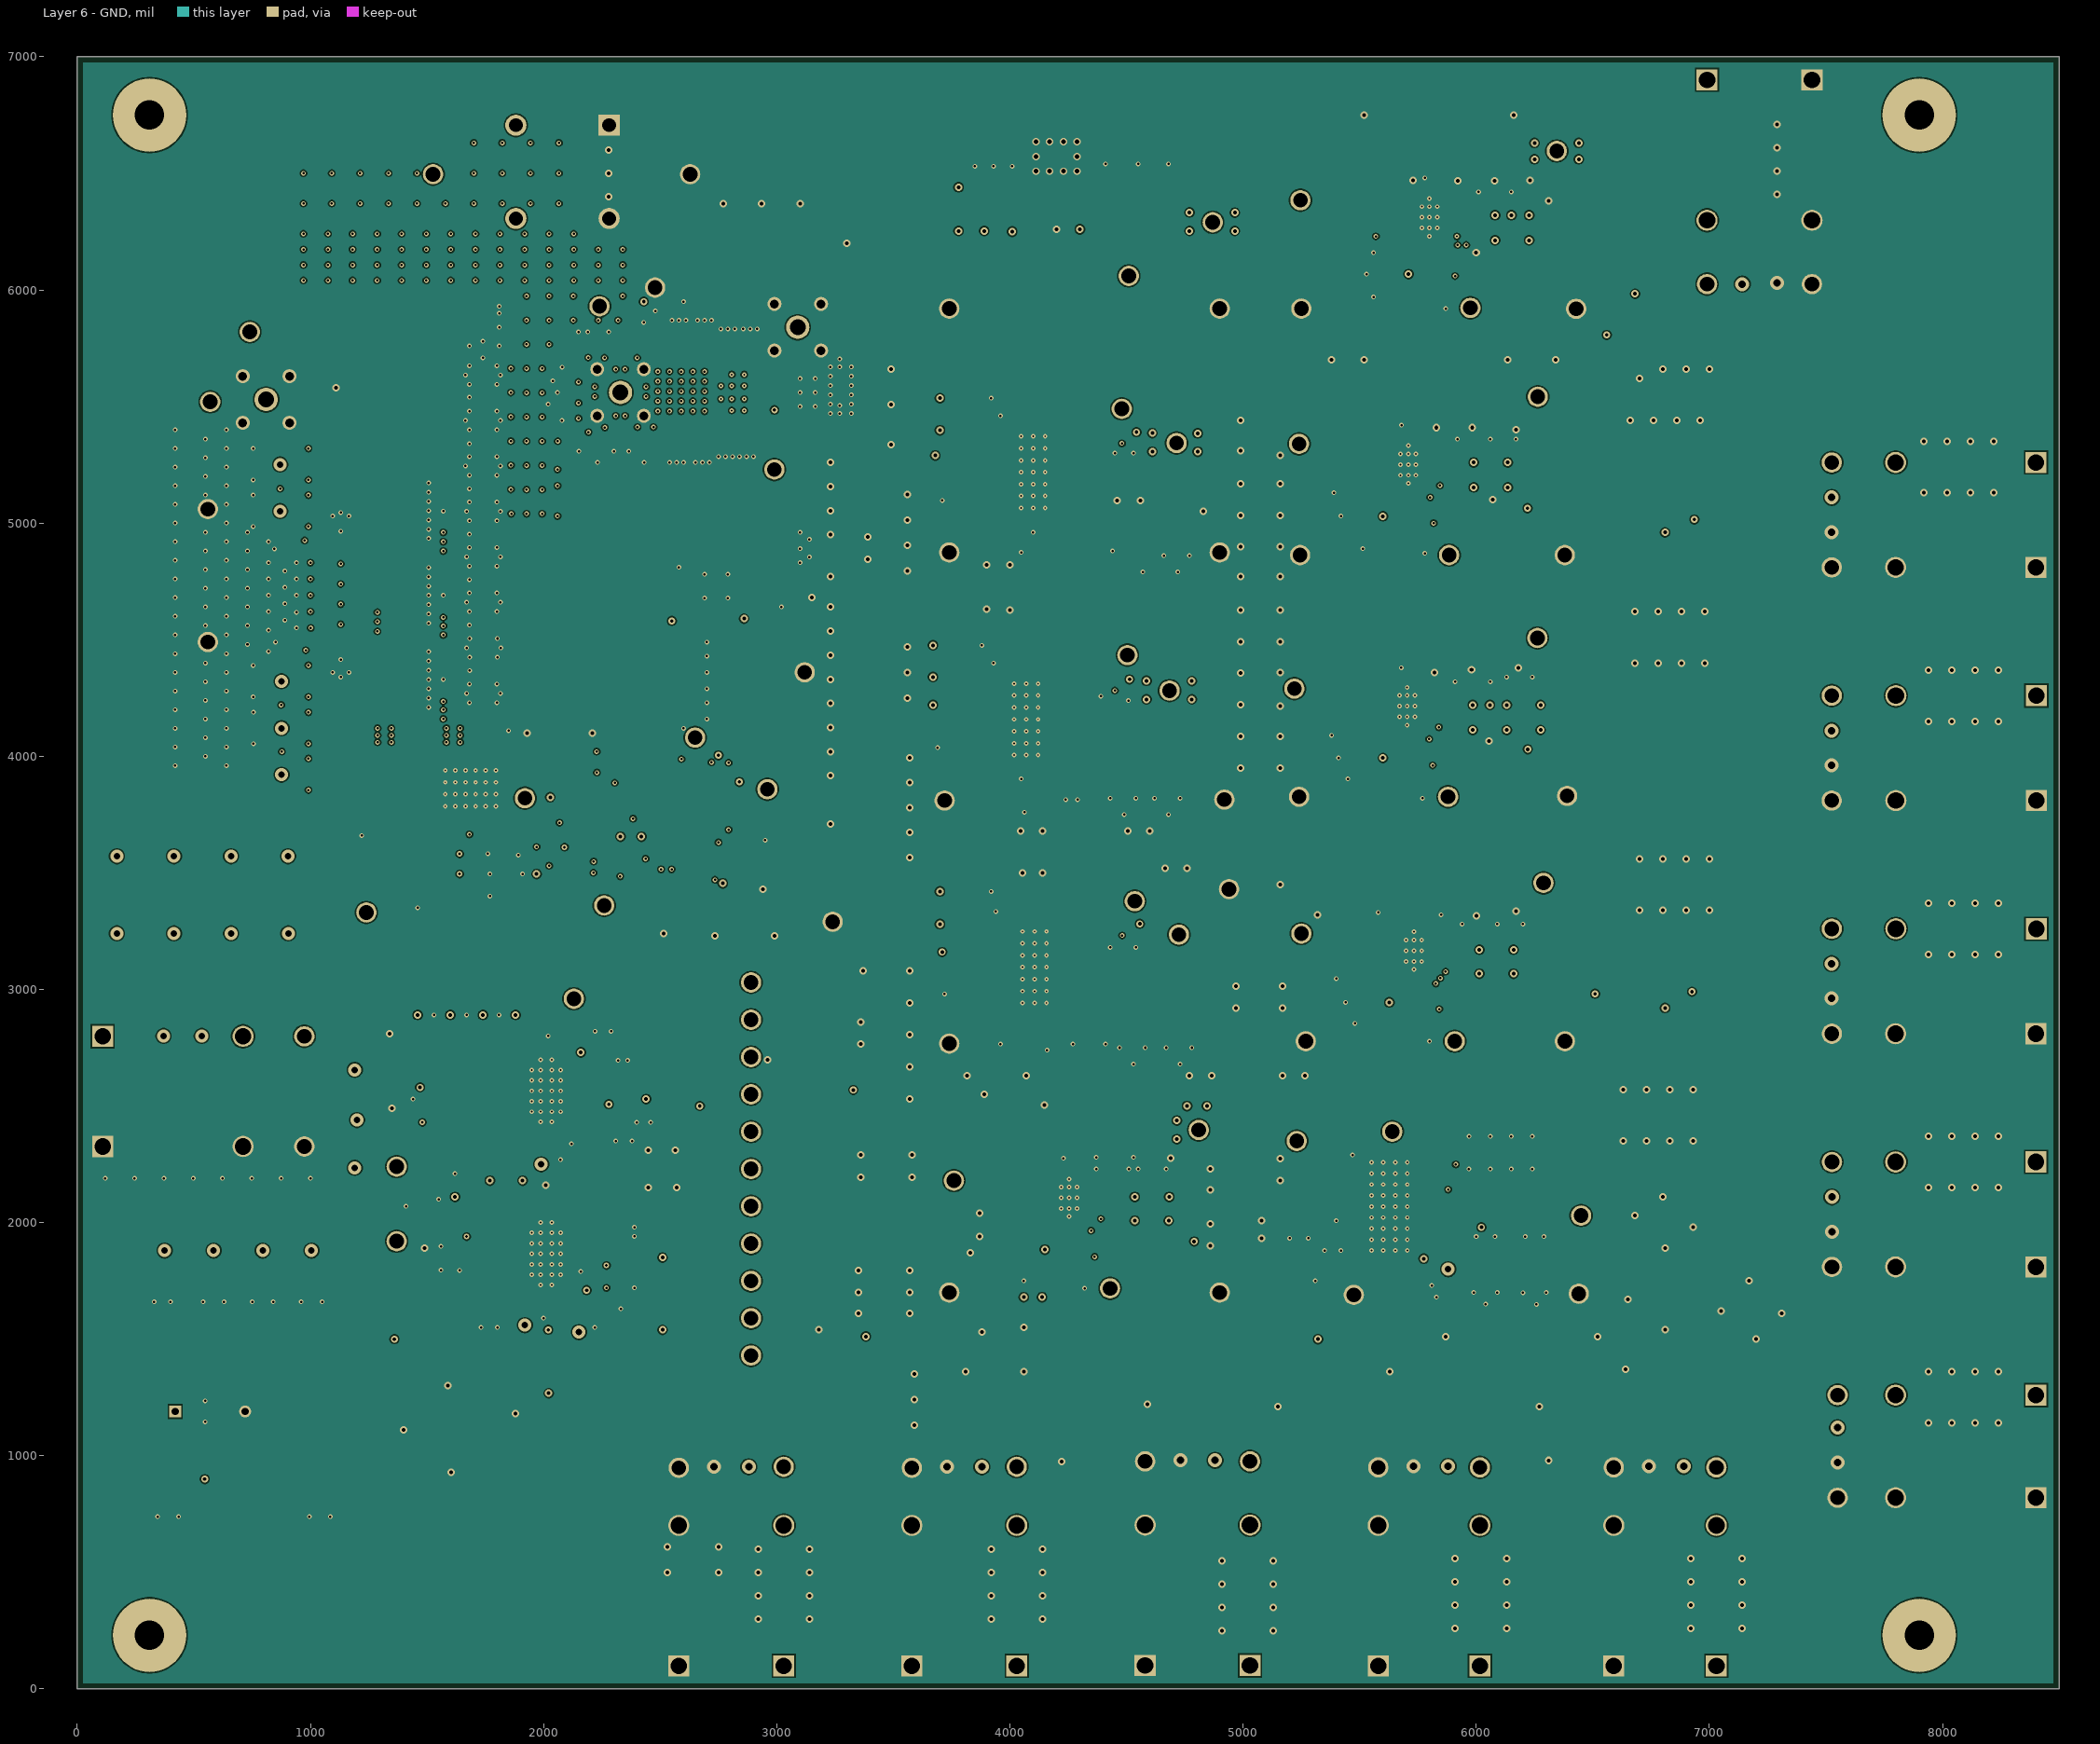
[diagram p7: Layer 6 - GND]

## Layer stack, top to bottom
Top Solder: solder mask 0.4, Solder Resist, Dk 3.3
Top Layer: signal copper 2.8
Dielectric 1: prepreg 3, FR-4 High Tg, Dk 4.2
Layer 1 - GND: signal copper 1.4
Dielectric 2: core 8, FR-4 High Tg, Dk 4.2
Signal Layer 2: signal copper 1.4
Dielectric 3: prepreg 8, FR-4 High Tg, Dk 4.2
Layer 3 - GND: signal copper 1.4
Dielectric 4: core 9.6, FR-4 High Tg, Dk 4.2
Layer 4 - Power: signal copper 1.4
Dielectric 5: prepreg 8, FR-4 High Tg, Dk 4.2
Signal Layer 5: signal copper 1.4
Dielectric 6: core 8, FR-4 High Tg, Dk 4.2
Layer 6 - GND: signal copper 1.4
Dielectric 7: prepreg 3, FR-4 High Tg, Dk 4.2
Bottom Layer: signal copper 2.8
Bottom Solder: solder mask 0.4, Solder Resist, Dk 3.3

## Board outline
0,0 8500,0 8500,7000 0,7000

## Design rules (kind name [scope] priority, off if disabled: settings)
AcuteAngle [All] p1: minimum=4.50000000000000E+0001 checktracksonly=FALSE
AssemblyTestPointUsage [All] p1: valid=2
BoardOutlineClearance BoardOutlineClearance_CONNECTOR [HasFootprint('Emerson_142-0701-851') OR HasFootprint('ON-Shore_ED120_2DS') OR HasFootprint('FP-1929517_HDR2-MFG')] p1: gap=10 ignorepadtopadclearanceinfootprint=FALSE except(0: Arc-SplitContinuation Track-OutlineEdge Track-CavityEdge Track-CutoutEdge Track-SplitBarrior Track-SplitContinuation SMDPad-SplitContinuation THPad-SplitContinuation Via-SplitContinuation Fill-SplitContinuation Poly-SplitContinuation Region-SplitContinuation Text-SplitContinuation)
BoardOutlineClearance BoardOutlineClearance_MountingHoles [OnCopper and InComponentClass('Mounting Holes')] p2: gap=25 ignorepadtopadclearanceinfootprint=FALSE
BoardOutlineClearance BoardOutlineClearance_Poly [OnCopper and InPoly] p3: gap=25 ignorepadtopadclearanceinfootprint=FALSE
BoardOutlineClearance [OnCopper and Not InComponentClass('Logo') and not InComponentClass('FiducialMark') and not InRegion(1000,500,4000,800)] p4: gap=25 ignorepadtopadclearanceinfootprint=FALSE
Clearance Clearance_Logo [(InComponent('FID1') OR InComponent('FID2') OR InComponent('FID3'))] p1: gap=0 ignorepadtopadclearanceinfootprint=TRUE
Clearance Clearance_1 [All] p2: gap=6 ignorepadtopadclearanceinfootprint=FALSE except(0: Arc-Hole Track-Hole SMDPad-Hole THPad-Hole Via-Hole Fill-Hole Poly-Hole Region-Hole Text-Hole)
Clearance Clearance_Keepouts [((IsTrack Or IsArc) And Not InPoly) And IsFree and IsKeepOut vs ((IsTrack Or IsArc) And Not InPoly) And IsFree and IsKeepOut] p3: gap=0 ignorepadtopadclearanceinfootprint=FALSE
Clearance Clearance_Poly [InPolygon] p4: gap=6 ignorepadtopadclearanceinfootprint=FALSE
ComponentClearance ComponentClearance_MountingHoles_FiducialMarks [InComponentClass('Mounting Holes') vs InComponentClass('FiducialMark')] p1: gap=30 collisioncheckmode=3 verticalgap=10 showdistances=FALSE
ComponentClearance ComponentClearance_Shunt [InComponentClass('Header') vs InComponentClass('Shunt')] p2: gap=0 collisioncheckmode=3 verticalgap=0 showdistances=FALSE
ComponentClearance ComponentClearance_Logo [InComponentClass('Logo')] p3: gap=10 collisioncheckmode=3 verticalgap=10 showdistances=FALSE
ComponentClearance ComponentClearance_ScrewToNut [(HasFootprint('NY PMS 440 0025 PH')) vs (HasFootprint('Keystone_1902C'))] p4: gap=5 collisioncheckmode=3 verticalgap=10 showdistances=FALSE
ComponentClearance ComponentClearance_MountingHoles [InComponentClass('Mounting Holes')] p5: gap=100 collisioncheckmode=3 verticalgap=100000 showdistances=TRUE
ComponentClearance ComponentClearance_SmallPassives [HasFootprint('0201*') or HasFootprint('0402*') or HasFootprint('0508') or HasFootprint('0603*') or HasFootprint('0612') or HasFootprint('0805*') or HasFootprint('0815*') or HasFootprint('0830*') or HasFootprint('1206*') or HasFootprint('1210*') or HasFootprint('1808*') or HasFootprint('1812*') or HasFootprint('1825*') or HasFootprint('2010*') or HasFootprint('2220*') or HasFootprint('2225*') or HasFootprint('2512*') or HasFootprint('2728*') or HasFootprint('3518*') vs HasFootprint('0201*') or HasFootprint('0402*') or HasFootprint('0508') or HasFootprint('0603*') or HasFootprint('0612') or HasFootprint('0805*') or HasFootprint('0815*') or HasFootprint('0830*') or HasFootprint('1206*') or HasFootprint('1210*') or HasFootprint('1808*') or HasFootprint('1812*') or HasFootprint('1825*') or HasFootprint('2010*') or HasFootprint('2220*') or HasFootprint('2225*') or HasFootprint('2512*') or HasFootprint('2728*') or HasFootprint('3518*')] p6: gap=14 collisioncheckmode=3 verticalgap=10 showdistances=FALSE
ComponentClearance ComponentClearance_THtoSMT [IsThruComponent vs IsSMTComponent] p7: gap=15 collisioncheckmode=3 verticalgap=30 showdistances=FALSE
ComponentClearance ComponentClearance_THtoTH [IsThruComponent vs IsThruComponent] p8: gap=15 collisioncheckmode=3 verticalgap=30 showdistances=FALSE
ComponentClearance [All] p9: gap=15 collisioncheckmode=3 verticalgap=10 showdistances=FALSE
DiffPairsRouting [All] p1: maxlimit=100 minlimit=10 mostfreqgap=10 toplayer_minwidth=15 toplayer_maxwidth=15 toplayer_prefwidth=15 midlayer1_minwidth=15 midlayer1_maxwidth=15 midlayer1_prefwidth=15 midlayer2_minwidth=15 midlayer2_maxwidth=15 midlayer2_prefwidth=15 midlayer3_minwidth=15 midlayer3_maxwidth=15 midlayer3_prefwidth=15 midlayer4_minwidth=15 midlayer4_maxwidth=15 midlayer4_prefwidth=15 midlayer5_minwidth=15 midlayer5_maxwidth=15 midlayer5_prefwidth=15 midlayer6_minwidth=15 midlayer6_maxwidth=15 midlayer6_prefwidth=15 bottomlayer_minwidth=15 bottomlayer_maxwidth=15 bottomlayer_prefwidth=15 maxuncoupledlength=1000
FabricationTestPointUsage TestPointUsage [All] p1: valid=2 allowmultiple=FALSE
FabricationTestpoint Testpoint [All] p1: side=3 testpointundercomponent=TRUE minsize=40 maxsize=100 preferedsize=60 minholesize=0 maxholesize=40 preferedholesize=32 testpointgrid=1 allowsidetop=TRUE allowsidebottom=TRUE usegrid=TRUE gridtolerance=0.01
FanoutControl Fanout_LCC [IsLCC] p1: bgadir=Out bgaviamode=Centered fanoutstyle=Auto fanoutdirection=Alternating viagrid=1 // Fanout_LCC (Default Rule)
FanoutControl Fanout_BGA [IsBGA] p2: bgadir=Out bgaviamode=Centered fanoutstyle=Auto fanoutdirection=Alternating viagrid=1 // Fanout_BGA (Default Rule)
FanoutControl Fanout_Default [All] p4: bgadir=Out bgaviamode=Centered fanoutstyle=Auto fanoutdirection=Alternating viagrid=1 // Fanout_Default (Default Rule)
FanoutControl Fanout_Small [(CompPinCount < 5)] p5: bgadir=Out bgaviamode=Centered fanoutstyle=Auto fanoutdirection=OutThenIn viagrid=1 // Fanout_Small (Default Rule)
HoleSize HoleSize_TEMP [All] p1: absolutevalues=TRUE maxlimit=251 minlimit=7.87 maxpercent=80.000 minpercent=20.000
HoleSize [All] p2: absolutevalues=TRUE maxlimit=251 minlimit=10 maxpercent=80.000 minpercent=20.000
MinimumAnnularRing MinimumAnnularRing_ThermalPadVias [IsVia and InAnyComponent] p1: minimumring=5
MinimumAnnularRing [All] p2: minimumring=5
MinimumSolderMaskSliver MinimumSolderMaskSliver_Logo [InComponentClass('Logo') vs InComponentClass('Logo')] p1: minsoldermaskwidth=0.7
MinimumSolderMaskSliver MinimumSolderMaskSliver_Temp [All] p2: minsoldermaskwidth=0.2
MinimumSolderMaskSliver [All] p3: minsoldermaskwidth=3.94
PlaneConnect [All] p1: planeconnectstyle=Direct reliefexpansion=10 reliefentries=4 reliefconductorwidth=10 reliefairgap=10
PolygonConnect [All] p1: connectstyle=Direct reliefconductorwidth=10 reliefentries=4 polygonreliefangle="90 Angle" airgapwidth=10
RoutingVias ThermalPadVias_TEMP [IsVia and InAnyComponent] p1: holewidth=10 width=19.68 viastyle="Through Hole" minholewidth=7.87 minwidth=19.68 maxholewidth=20 maxwidth=32
RoutingVias ThermalPadVias [IsVia and InAnyComponent] p2: holewidth=10 width=20 viastyle="Through Hole" minholewidth=10 minwidth=19.68 maxholewidth=12.99 maxwidth=23.62
RoutingVias RoutingVias_temp [All] p3: holewidth=16 width=32 viastyle="Through Hole" minholewidth=7.87 minwidth=19 maxholewidth=50 maxwidth=100
RoutingVias [All] p4: holewidth=16 width=32 viastyle="Through Hole" minholewidth=10 minwidth=20 maxholewidth=50 maxwidth=100
SilkToBoardRegionClearance [Not ((IsComment or IsDesignator) And (Hide <> 'False')) and not InRegion(1000,500,4000,800)] p1:
SilkToSilkClearance SilkToSilkClearance_Pb-FreeLogo [(HasFootprint('Pb-Free_Overlay_Medium') OR HasFootprint('Pb-Free_Overlay_Small')) vs (HasFootprint('Pb-Free_Overlay_Medium') OR HasFootprint('Pb-Free_Overlay_Small'))] p1: silktosilkclearance=0
SilkToSilkClearance SilkToSilkClearance_Temp [All] p2: silktosilkclearance=0.1
SilkToSilkClearance [All] p3: silktosilkclearance=3
SilkToSolderMaskClearance SilkToComponentPadClearance_TEMP [IsPad and InAnycomponent] p1: minsilkscreentomaskgap=0.2 clearancetoexposedcopper=TRUE
SilkToSolderMaskClearance SilkToComponentPadClearance [IsPad and InAnycomponent] p2: minsilkscreentomaskgap=4 clearancetoexposedcopper=TRUE
SilkToSolderMaskClearance "Silk to Solder Mask Opening_TEMP" [All] p3: minsilkscreentomaskgap=0.01 clearancetoexposedcopper=FALSE
SilkToSolderMaskClearance "Silk to Solder Mask Opening" [All] p4: minsilkscreentomaskgap=3 clearancetoexposedcopper=FALSE
SolderMaskExpansion [All] p1: expansion=1.97 istentingtop=FALSE
Width [All] p1: maxlimit=100 minlimit=6 preferedwidth=10 checkconnectedcopper=TRUE
15 further rules are at their usual default settings.

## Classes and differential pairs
component class TIDA-050088_Sequencing: C80 C81 C82 C83 C84 C85 C86 C87 C88 C89 C90 C91 C92 C93 C94 C95 C96 C97 C98 Q6 R39 R40 R41 R42 R43 R44 R45 R46 R47 R48 R49 R50 R51 R52 R53 R54 R55 R56 R57 R58 R59 R60 R61 R62 R63 R64 R65 R66 R67 R68 R69 R70 R71 R72 R73 R74 R75 R76 R77 R78 SW1 TP19 TP20 TP21 TP22 TP23 TP24 TP25 TP26 TP27 TP28 TP29 TP30 TP31 TP32 U3 U4 U5 U6 U7 U8 U9 U10 U11 U12
component class TIDA-050088_Bucks: C145 C146 C147 C148 C149 C150 C151 C152 C153 C154 C155 C156 C157 C158 C159 C160 C161 C162 C163 C164 C165 C166 C167 C168 C169 C170 C171 C172 C173 C174 C175 C176 C177 C178 C179 C180 C181 C182 C183 C184 C185 C186 C187 C188 C189 C190 C191 C192 C193 C194 C195 C196 J25 J26 J27 J28 J29 J30 J31 J32 J33 J34 J35 J36 J37 J38 J39 L2 L3 L4 L5 L6 R117 R118 R119 R120 R121 R122 R123 R124 R125 R126 R127 R128 R129 R130 R131 R132 R133 R134 R135 R136 R137 R138 R139 R140 R141 TP66 TP67 TP68 TP69 TP70 TP71 TP72 TP73 TP74 TP75 TP76 TP77 TP78 TP79 TP80 TP81 TP82 TP83 TP84 TP85 TP86 TP87 TP88 TP89 TP90 TP91 TP92 TP93 TP94 TP95 TP96 TP97 TP98 TP99 TP100 U18 U19 U20 U21 U22
component class TIDA-050088_Aux: D4 D5 R115 R116 SW2 SW3
component class TIDA-050088_LDOs: C99 C100 C101 C102 C103 C104 C105 C106 C107 C108 C109 C110 C111 C112 C113 C114 C115 C116 C117 C118 C119 C120 C121 C122 C123 C124 C125 C126 C127 C128 C129 C130 C131 C132 C133 C134 C135 C136 C137 C138 C139 C140 C141 C142 C143 C144 FB1 J8 J9 J10 J11 J12 J13 J14 J15 J16 J17 J18 J19 J20 J21 J22 J23 J24 R79 R80 R81 R82 R83 R84 R85 R86 R87 R88 R89 R90 R91 R92 R93 R94 R95 R96 R97 R98 R99 R100 R101 R102 R103 R104 R105 R106 R107 R108 R109 R110 R111 R112 R113 R114 TP33 TP34 TP35 TP36 TP37 TP38 TP39 TP40 TP41 TP42 TP43 TP44 TP45 TP46 TP47 TP48 TP49 TP50 TP51 TP52 TP53 TP54 TP55 TP56 TP57 TP58 TP59 TP60 TP61 TP62 TP63 TP64 TP65 U13 U14 U15 U16 U17
component class TIDA-050088_Core: C1 C2 C3 C4 C5 C6 C7 C8 C9 C10 C11 C12 C13 C14 C15 C16 C17 C18 C19 C20 C21 C22 C23 C24 C25 C26 C27 C28 C29 C30 C31 C32 C33 C34 C35 C36 C37 C38 C39 C40 C41 C42 C43 C44 C45 C46 C47 C48 C49 C50 C51 C52 C53 C54 C55 C56 C57 C58 C59 C60 C61 C62 C63 C64 C65 C66 C67 C68 C69 C70 C71 C72 C73 C74 C75 C76 C77 C78 C79 D1 D2 D3 J1 J2 J3 J4 J5 J6 J7 L1 Q1 Q2 Q3 Q4 Q5 R1 R2 R3 R4 R5 R6 R7 R8 R9 R10 R11 R12 R13 R14 R15 R16 R17 R18 R19 R20 R21 R22 R23 R24 R25 R26 R27 R28 R29 R30 R31 R32 R33 R34 R35 R36 R37 R38 TP1 TP2 TP3 TP4 TP5 TP6 TP7 TP8 TP9 TP10 TP11 TP12 TP13 TP14 TP15 TP16 TP17 TP18 U1
component class "Mounting Holes": H1 H2 H3 H4
component class Logo: Logo1
component class TIDA-050088_Hardware: FID1 FID2 FID3 H1 H2 H3 H4 H5 H6 H7 H8 Logo1 Logo2 Logo3 Logo4 ZZ1 ZZ2 ZZ3 ZZ4
component class FiducialMark: FID1 FID2 FID3
component class AssemblyNote: ZZ1 ZZ2 ZZ3 ZZ4

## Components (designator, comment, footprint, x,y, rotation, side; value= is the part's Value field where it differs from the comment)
C1 "T521D157M020ATE050" FP-T521D157M020ATE050_2917-MFG 873.28,4121.3 r180 top value=150µF
C2 "T521D157M020ATE050" FP-T521D157M020ATE050_2917-MFG 873.28,3921.3 r180 top value=150µF
C3 "T521D157M020ATE050" FP-T521D157M020ATE050_2917-MFG 873.28,5251.3 r180 top value=150µF
C4 "T521D157M020ATE050" FP-T521D157M020ATE050_2917-MFG 873.28,4321.3 r180 top value=150µF
C5 "T521D157M020ATE050" FP-T521D157M020ATE050_2917-MFG 873.28,5051.3 r180 top value=150µF
C6 "GCM32ER71E106KA57L" 1210_280 960,4490 r180 top value=10uF
C7 "GCM32ER71E106KA57L" 1210_280 950,4888.94 r180 top value=10uF
C8 "GCM32ER71E106KA57L" 1210_280 620,3810 r90 top value=10uF
C9 "GCM188R71E104KA57D" 0603 1165.02,4433.72 r270 top value=0.1uF
C10 "GCM188R71E104KA57D" 0603 1095.02,4433.72 r270 top value=0.1uF
C11 "GCM188R71E104KA57D" 0603 1095.02,4950 r90 top value=0.1uF
C12 "GCM188R71E104KA57D" 0603 1165,4950 r90 top value=0.1uF
C13 "GCM188R71E104KA57D" 0603 968.5,4793.94 r180 top value=0.1uF
C14 "GCM188R71E104KA57D" 0603 968.5,4583.94 r180 top value=0.1uF
C15 "GCM188R71E104KA57D" 0603 970,4653.94 r180 top value=0.1uF
C16 "GCM188R71E104KA57D" 0603 970,4723.94 r180 top value=0.1uF
C17 "C0805C105K4RACAUTO" 0805_HV 2090,3570.04 r270 top value=1uF
C18 "GCM188R71E104KA57D" 0603 2170,3580.04 r270 top value=0.1uF
C19 "C0805C105K4RACAUTO" 0805_HV 2620,3535.59 r270 top value=1uF
C20 "C0603C151J5GACTU" 0603 2700,3550.04 r270 top value=150pF
C21 "GRM1885C2A560JA01D" 0603 2535,3955.89 r90 top value=56pF
C22 "C0603C223K5RACTU" 0603 2490,4090 r0 top value=0.022uF
C23 "GCM188R71E474KA64D" 0603 2610,3718.09 r270 top value=0.47uF
C24 "06035C563KAT2A" 0603 2750,3718.09 r270 top value=0.056uF
C25 "885012006012" 0603 2566.5,3405 r0 top value=470pF
C26 "GRM219R7YA105KA12D" 0805_HV 1680,3495 r0 top value=1uF
C27 "GRM219R7YA105KA12D" 0805_HV 1680,3580.84 r0 top value=1uF
C28 "C0805C105K4RACAUTO" 0805_HV 1680,3400 r0 top value=1uF
C29 "C0805C105K4RACAUTO" 0805_HV 1445.79,4110 r0 top value=1uF
C30 "06035C104KAZ2A" 0603 1445.79,3602.75 r0 top value=0.1uF
C31 "GRM219R7YA105KA12D" 0805_HV 1460,3510 r0 top value=1uF
C32 "T520X158M2R5ATE015" FP-T520X158M2R5ATE015_2917-MFG 1860,4270 r0 top value=1.5mF
C33 "T520X158M2R5ATE015" FP-T520X158M2R5ATE015_2917-MFG 1860,4465 r0 top value=1.5mF
C34 "T520X158M2R5ATE015" FP-T520X158M2R5ATE015_2917-MFG 1860,4660 r0 top value=1.5mF
C35 "T520X158M2R5ATE015" FP-T520X158M2R5ATE015_2917-MFG 1860,4855 r0 top value=1.5mF
C36 "T520X158M2R5ATE015" FP-T520X158M2R5ATE015_2917-MFG 1860,5050 r0 top value=1.5mF
C37 "T520X158M2R5ATE015" FP-T520X158M2R5ATE015_2917-MFG 1860,5245 r0 top value=1.5mF
C38 "T520X158M2R5ATE015" FP-T520X158M2R5ATE015_2917-MFG 1860,5635 r0 top value=1.5mF
C39 "T520X158M2R5ATE015" FP-T520X158M2R5ATE015_2917-MFG 1860,5440 r0 top value=1.5mF
C40 "T520X158M2R5ATE015" FP-T520X158M2R5ATE015_2917-MFG 2510,4450 r180 top value=1.5mF
C41 "T520X158M2R5ATE015" FP-T520X158M2R5ATE015_2917-MFG 2510,4250 r180 top value=1.5mF
C42 "C0603X104K3RACTU" 0603 1050,5650 r270 top value=0.1uF
C43 "C0805C105K4RACAUTO" 0805_HV 1750,4110 r0 top value=1uF
C44 "T521D157M020ATE050" FP-T521D157M020ATE050_2917-MFG 375,1840 r270 top value=150µF
C45 "T521D157M020ATE050" FP-T521D157M020ATE050_2917-MFG 585,1840 r270 top value=150µF
C46 "T521D157M020ATE050" FP-T521D157M020ATE050_2917-MFG 795,1840 r270 top value=150µF
C47 "T521D157M020ATE050" FP-T521D157M020ATE050_2917-MFG 1005,1840 r270 top value=150µF
C48 "CL32B226KOJNFNE" 1210_270 1920,5940 r180 top value=22uF
C49 "CL32B226KOJNFNE" 1210_270 1920,5800 r180 top value=22uF
C50 "CL32B226KOJNFNE" 1210_270 2421.14,5830 r0 top value=22uF
C51 "C3216X7R1A106K085AC" 1206 2580,5760.03 r90 top value=10uF
C52 "C3216X7R1A106K085AC" 1206 2690,5760 r90 top value=10uF
C53 "C3216X7R1A106K085AC" 1206 2681.14,5367.09 r270 top value=10uF
C54 "C3216X7R1A106K085AC" 1206 2570,5367.09 r270 top value=10uF
C55 "885012207025" 0805_HV 2886.73,5740 r90 top value=4.7uF
C56 "885012207025" 0805_HV 2790,5740 r90 top value=4.7uF
C57 "885012207025" 0805_HV 2790,5385 r270 top value=4.7uF
C58 "885012207025" 0805_HV 2880,5385 r270 top value=4.7uF
C59 "GRM21BR71A225KA01L" 0805_HV 2790,5753.53 r90 bottom value=2.2uF
C60 "GRM21BR71A225KA01L" 0805_HV 2790,5371.5 r270 bottom value=2.2uF
C61 "GRM21BR71A225KA01L" 0805_HV 2700,5753.53 r90 bottom value=2.2uF
C62 "C0805C105K4RACAUTO" 0805_HV 2610,5371.5 r270 bottom value=1uF
C63 "C0805C105K4RACAUTO" 0805_HV 2520,5753.53 r90 bottom value=1uF
C64 "C0805C105K4RACAUTO" 0805_HV 2610,5753.53 r90 bottom value=1uF
C65 "C0805C105K4RACAUTO" 0805_HV 2100,5560 r180 bottom value=1uF
C66 "C0805C105K4RACAUTO" 0805_HV 2700,5371.5 r270 bottom value=1uF
C67 "C0805C105K4RACAUTO" 0805_HV 2520,5371.5 r270 bottom value=1uF
C68 "C0603C474K8RACTU" 0603 2364.05,5385 r270 bottom value=0.47uF
C69 "C0603C474K8RACTU" 0603 2430,5340 r270 bottom value=0.47uF
C70 "C0603C474K8RACTU" 0603 2300,5385 r270 bottom value=0.47uF
C71 "C0603C474K8RACTU" 0603 2299.93,5740 r90 bottom value=0.47uF
C72 "C0603C474K8RACTU" 0603 2363.98,5740 r90 bottom value=0.47uF
C73 "C0603C474K8RACTU" 0603 2429.93,5780 r90 bottom value=0.47uF
C74 "885012206020" 0603 2110,5637.17 r180 bottom value=0.1uF
C75 "885012206020" 0603 2151.36,5740 r90 bottom value=0.1uF
C76 "885012206020" 0603 2230.75,5780 r90 bottom value=0.1uF
C77 "885012206020" 0603 2230.75,5340 r270 bottom value=0.1uF
C78 "885012206020" 0603 2151.43,5380 r270 bottom value=0.1uF
C79 "885012206020" 0603 2110,5482.83 r180 bottom value=0.1uF
C80 "GRM219R7YA105KA12D" 0805_HV 2030,2338.05 r0 top value=1uF
C81 "GRM219R7YA105KA12D" 0805_HV 2340,2620 r90 top value=1uF
C82 "GRM219R7YA105KA12D" 0805_HV 2440,2520 r270 top value=1uF
C83 "GRM219R7YA105KA12D" 0805_HV 2340,2450 r270 top value=1uF
C84 "C0603C474K8RACTU" 0603 2189.24,2777.92 r0 top value=0.47uF
C85 "C0805C155K8RACTU" 0805_HV 1620,2310 r270 top value=1.5uF
C86 "0805YC474JAT2A" 0805_HV 1690,2530 r270 top value=0.47uF
C87 "GRM219R7YA105KA12D" 0805_HV 1960,1650 r0 top value=1uF
C88 "GRM219R7YA105KA12D" 0805_HV 2331.99,1920 r90 top value=1uF
C89 "GRM219R7YA105KA12D" 0805_HV 2430,1834.75 r270 top value=1uF
C90 "GRM219R7YA105KA12D" 0805_HV 2331.99,1760 r90 top value=1uF
C91 "0805YC474JAT2A" 0805_HV 1691.99,1835.55 r270 top value=0.47uF
C92 "C0603C474K8RACTU" 0603 6650,5913.24 r180 top value=0.47uF
C93 "C0603C474K8RACTU" 0603 3450,1480 r270 top value=0.47uF
C94 "C0603C474K8RACTU" 0603 2081.99,1238.02 r270 top value=0.47uF
C95 "C0603X104K3RACTU" 0603 2559.7,4688.5 r90 top value=0.1uF
C96 "C0603C474K8RACTU" 0603 6920,4960 r0 top value=0.47uF
C97 "C0603C474K8RACTU" 0603 5381.47,1470 r270 top value=0.47uF
C98 "C0603C474K8RACTU" 0603 6910,2920 r0 top value=0.47uF
C99 "TRME107K020R0035" FP-TRME107K020R0035_2917-MFG 4513.62,5068.66 r90 top value=100µF
C100 "TRME107K020R0035" FP-TRME107K020R0035_2917-MFG 4713.67,5067.12 r90 top value=100µF
C101 "TRME107K020R0035" FP-TRME107K020R0035_2917-MFG 4483.62,4008.66 r90 top value=100µF
C102 "TRME107K020R0035" FP-TRME107K020R0035_2917-MFG 4683.67,4007.12 r90 top value=100µF
C103 "C1608X7R1E104K080AA" 0603 4861.9,5173.13 r270 top value=0.1uF
C104 "T520A106M010ATE080" 3216-18 3784.47,5148.33 r270 top value=10uF
C105 "885012206071" 0603 3877.98,5167.03 r270 top value=0.1uF
C106 "C1608X7R1E104K080AA" 0603 4831.9,4113.13 r270 top value=0.1uF
C107 "T520A106M010ATE080" 3216-18 3754.47,4088.33 r270 top value=10uF
C108 "885012206071" 0603 3847.98,4107.03 r270 top value=0.1uF
C109 "GCM188R71E104KA57D" 0603 4482.31,1099.57 r270 top value=0.1uF
C110 "C1206C225K4RAC7800" FP-C1206C225K4RAC7800_1206-MFG 4159.97,4874.21 r180 top value=2.2µF
C111 "T520A106M010ATE080" 3216-18 3815.6,5535.74 r0 top value=10uF
C112 "08053A472JAT2A" 0805_HV 4347.96,5114.04 r270 top value=4700pF
C113 "C1206C225K4RAC7800" FP-C1206C225K4RAC7800_1206-MFG 4129.97,3814.21 r180 top value=2.2µF
C114 "12063C475KAT2A" 1206_180 3866.03,5382.38 r90 top value=4.7uF
C115 "T520A106M010ATE080" 3216-18 3785.6,4475.74 r0 top value=10uF
C116 "08053A472JAT2A" 0805_HV 4317.96,4054.04 r270 top value=4700pF
C117 "12063C475KAT2A" 1206_180 3836.03,4322.38 r90 top value=4.7uF
C118 "TRME107K020R0035" FP-TRME107K020R0035_2917-MFG 4525.05,2953.41 r90 top value=100µF
C119 "TRME107K020R0035" FP-TRME107K020R0035_2917-MFG 4725.1,2951.87 r90 top value=100µF
C120 "C0603X102K5RACTU" 0603 5850,2365 r0 top value=1000pF
C121 "C1608X7R1E104K080AA" 0603 4863.33,3057.88 r270 top value=0.1uF
C122 "T520A106M010ATE080" 3216-18 3785,3033.82 r270 top value=10uF
C123 "885012206071" 0603 3879.4,3051.78 r270 top value=0.1uF
C124 "GCM31CR71C475KA37L" 1206_180 5880,1794.02 r270 top value=4.7uF
C125 "T530D157M010ATE005" 7343-31 6400,2310 r90 top value=150uF
C126 "T530D157M010ATE005" 7343-31 6040,1940 r270 top value=150uF
C127 "T530D157M010ATE005" 7343-31 6250,1940 r270 top value=150uF
C128 "GCM31CR71C475KA37L" 1206_180 6060,2230 r90 top value=4.7uF
C129 "GCM31CR71C475KA37L" 1206_180 5968.12,2230.72 r90 top value=4.7uF
C130 "GCM31CR71C475KA37L" 1206_180 6150,2230 r90 top value=4.7uF
C131 "GCM31CR71C475KA37L" 1206_180 6240,2230 r90 top value=4.7uF
C132 "T520D227M010ATE018" 7343-31 5240,1955 r270 top value=220uF
C133 "GCM31CR71C475KA37L" 1206_180 5400,2020 r270 top value=4.7uF
C134 "C1608X7R1E104K080AA" 0603 5380,2225 r90 top value=0.1uF
C135 "C1206C225K4RAC7800" FP-C1206C225K4RAC7800_1206-MFG 4161.4,2758.96 r180 top value=2.2µF
C136 "T520A106M010ATE080" 3216-18 3817.03,3420.49 r0 top value=10uF
C137 "08053A472JAT2A" 0805_HV 4349.39,2998.79 r270 top value=4700pF
C138 "12063C475KAT2A" 1206_180 3867.45,3267.13 r90 top value=4.7uF
C139 "885012209028" 1210_220 3890,6380 r90 top value=10uF
C140 "CL21B474KAFNNNG" 0805_HV 4010,6360 r90 top value=0.47uF
C141 "CGA6P1X7R1C226M250AC" 1210_280 4550,6370 r90 top value=22uF
C142 "CGA6P1X7R1C226M250AC" 1210_280 4680,6370 r90 top value=22uF
C143 "T520B107M006ATE015" 3528-21 4410,6380 r90 top value=100uF
C144 "GCM1885C1H471JA16D" 0603 4310,6130 r180 top value=470pF
C145 "CL21B474KAFNNNG" 0805_HV 5494.69,3147.87 r180 top value=0.47uF
C146 "CL21B474KAFNNNG" 0805_HV 5470.4,5232.78 r180 top value=0.47uF
C147 "885012209028" 1210_220 6013.9,3179 r90 top value=10uF
C148 "885012209028" 1210_220 6159.31,3179 r90 top value=10uF
C149 "C0805C474K3RACAUTO" 0805_HV 5890.2,3196.2 r90 top value=0.47uF
C150 "885012209028" 1210_220 5989.61,5263.9 r90 top value=10uF
C151 "885012209028" 1210_220 6135.02,5263.9 r90 top value=10uF
C152 "C0805C474K3RACAUTO" 0805_HV 5865.91,5281.1 r90 top value=0.47uF
C153 "CGA6P1X7R1C226M250AC" 1210_280 5784.64,3399.74 r270 top value=22uF
C154 "CGA6P1X7R1C226M250AC" 1210_280 5651.56,3399.74 r270 top value=22uF
C155 "T520B107M006ATE015" 3528-21 6086.31,3393.04 r270 top value=100uF
C156 "T520B107M006ATE015" 3528-21 5929.57,3393.04 r270 top value=100uF
C157 "CGA6P1X7R1C226M250AC" 1210_280 5760.35,5484.64 r270 top value=22uF
C158 "T520B107M006ATE015" 3528-21 5905.28,5477.95 r270 top value=100uF
C159 "T520B107M006ATE015" 3528-21 6062.02,5477.95 r270 top value=100uF
C160 "C2012X7R1C225K125AB" 0805_HV 5506.5,3045.9 r180 top value=2.2uF
C161 "C2012X7R1C225K125AB" 0805_HV 5482.22,5130.81 r180 top value=2.2uF
C162 "GRM1885C1H360JA01D" 0603 5732.79,2908.21 r180 top value=36pF
C163 "GRM1885C1H360JA01D" 0603 5708.51,4993.11 r180 top value=36pF
C164 "C0805C105K4RACTU" 0805_HV 5538,2943.93 r180 top value=1uF
C165 "C0805C105K4RACTU" 0805_HV 5513.71,5028.84 r180 top value=1uF
C166 "CL21B474KAFNNNG" 0805_HV 5466.06,4196.32 r180 top value=0.47uF
C167 "CL21B474KAFNNNG" 0805_HV 4016.26,2087.99 r180 top value=0.47uF
C168 "885012209028" 1210_220 4535.46,2119.11 r90 top value=10uF
C169 "885012209028" 1210_220 4680.88,2119.11 r90 top value=10uF
C170 "C0805C474K3RACAUTO" 0805_HV 4411.77,2136.31 r90 top value=0.47uF
C171 "885012209028" 1210_220 5985.26,4227.45 r90 top value=10uF
C172 "885012209028" 1210_220 6130.68,4227.45 r90 top value=10uF
C173 "885012209028" 1210_220 6276.09,4226.85 r90 top value=10uF
C174 "C0805C474K3RACAUTO" 0805_HV 5861.56,4244.65 r90 top value=0.47uF
C175 "CGA6P1X7R1C226M250AC" 1210_280 5756,4448.19 r270 top value=22uF
C176 "T520B107M006ATE015" 3528-21 6057.68,4441.49 r270 top value=100uF
C177 "T520B107M006ATE015" 3528-21 5900.93,4441.49 r270 top value=100uF
C178 "CGA6P1X7R1C226M250AC" 1210_280 4306.21,2339.85 r270 top value=22uF
C179 "T520B107M006ATE015" 3528-21 4607.88,2333.15 r270 top value=100uF
C180 "T520B107M006ATE015" 3528-21 4451.14,2333.15 r270 top value=100uF
C181 "C2012X7R1C225K125AB" 0805_HV 5477.87,4094.35 r180 top value=2.2uF
C182 "C2012X7R1C225K125AB" 0805_HV 4028.07,1986.02 r180 top value=2.2uF
C183 "GRM1885C1H360JA01D" 0603 5704.16,3956.66 r180 top value=36pF
C184 "GRM1885C1H360JA01D" 0603 4254.36,1848.32 r180 top value=36pF
C185 "C0805C105K4RACTU" 0805_HV 5509.36,3992.38 r180 top value=1uF
C186 "C0805C105K4RACTU" 0805_HV 4059.57,1884.04 r180 top value=1uF
C187 "CL21B474KAFNNNG" 0805_HV 5478.41,6237.67 r180 top value=0.47uF
C188 "885012209028" 1210_220 6081.02,6324.12 r90 top value=10uF
C189 "885012209028" 1210_220 6226.44,6324.12 r90 top value=10uF
C190 "C0805C474K3RACAUTO" 0805_HV 5957.33,6341.32 r90 top value=0.47uF
C191 "CGA6P1X7R1C226M250AC" 1210_280 5851.77,6544.86 r270 top value=22uF
C192 "CGA6P1X7R1C226M250AC" 1210_280 6153.44,6538.16 r270 top value=22uF
C193 "T520B107M006ATE015" 3528-21 5996.7,6538.16 r270 top value=100uF
C194 "C2012X7R1C225K125AB" 0805_HV 5622.24,6203.67 r270 top value=2.2uF
C195 "GRM1885C1H101JA01D" 0603 5799.92,6053.33 r180 top value=100pF
C196 "C0805C105K4RACTU" 0805_HV 5629.65,6067.7 r180 top value=1uF
D1 "ES3AB-13-F" SMB 1170,3550 r180 top value=50V
D2 "BZT52B13-E3-08" FP-BZT52B13-E3-08_SOD123-MFG 1480.24,3410 r0 top
D3 "SK5C0A" FP-SK5C0A_SMA-MFG 1520,5290 r0 top
D4 "APHHS1005CGCK" APHHS1005_Green 187.72,1500 r180 top value=Green
D5 "APHHS1005CGCK" APHHS1005_Green 700,1500 r180 top value=Green
FB1 "BLM18EG221SN1D" FP-BLM18EG221SN1D_0603-MFG 4411.77,1102.52 r90 top
FID1 "Fiducial" Fiducial10-20 670,6750 r0 top
FID2 "Fiducial" Fiducial10-20 1530,240 r0 top
FID3 "Fiducial" Fiducial10-20 7870,6310 r0 top
H1 "NY PMS 440 0025 PH" "NY PMS 440 0025 PH" 310,6750 r0 top
H2 "NY PMS 440 0025 PH" "NY PMS 440 0025 PH" 7900,6750 r0 top
H3 "NY PMS 440 0025 PH" "NY PMS 440 0025 PH" 310,230 r0 top
H4 "NY PMS 440 0025 PH" "NY PMS 440 0025 PH" 7900,230 r0 top
H5 "1902C" Keystone_1902C 310,6750 r180 bottom
H6 "1902C" Keystone_1902C 7900,6750 r180 bottom
H7 "1902C" Keystone_1902C 310,230 r180 bottom
H8 "1902C" Keystone_1902C 7900,230 r180 bottom
J1 "SW" Tek_131-5031-00 810,5530 r0 top
J2 "1929517" FP-1929517_HDR2-MFG 2077.24,6614.17 r180 top
J3 "60312102114405" FP-60312102114405_CONN_SMA-MFG 1166.1,6753.7 r90 top
J4 "571-0500" 571-0500 410,2798.82 r0 top
J5 "571-0100" 571-0100 410,2326.38 r0 top
J6 "0V8" Tek_131-5031-00 2330,5560 r0 top
J7 "ISTEP" Tek_131-5031-00 3090,5840 r0 top
J8 "571-0500" 571-0500 3030,400 r90 top
J9 "571-0500" 571-0500 4029.48,400 r90 top
J10 "571-0500" 571-0500 5030,401.63 r90 top
J11 "60312102114405" FP-60312102114405_CONN_SMA-MFG 2213.7,963.9 r0 top
J12 "60312102114405" FP-60312102114405_CONN_SMA-MFG 3810,1234 r0 top
J13 "60312102114405" FP-60312102114405_CONN_SMA-MFG 4810,1234 r0 top
J14 "571-0100" 571-0100 4580,401.63 r90 top
J15 "571-0100" 571-0100 2580,400 r90 top
J16 "571-0100" 571-0100 3579.48,400 r90 top
J17 "571-0500" 571-0500 6016.12,400 r90 top
J18 "571-0500" 571-0500 7030,400 r90 top
J19 "60312102114405" FP-60312102114405_CONN_SMA-MFG 5800,1234 r0 top
J20 "571-0500" 571-0500 8100,1260 r180 top
J21 "60312102114405" FP-60312102114405_CONN_SMA-MFG 6806.3,1234 r0 top
J22 "571-0100" 571-0100 8100,820 r180 top
J23 "571-0100" 571-0100 5580,400 r90 top
J24 "571-0100" 571-0100 6590,400 r90 top
J25 "571-0500" 571-0500 8101.18,3260 r180 top
J26 "571-0500" 571-0500 8100,5260 r180 top
J27 "60312102114405" FP-60312102114405_CONN_SMA-MFG 7256,3036.69 r0 top
J28 "60312102114405" FP-60312102114405_CONN_SMA-MFG 7256,5040 r0 top
J29 "571-0100" 571-0100 8100,2810 r180 top
J30 "571-0100" 571-0100 8100,4810 r180 top
J31 "571-0500" 571-0500 8101.18,4260 r180 top
J32 "571-0500" 571-0500 8100,2260 r180 top
J33 "60312102114405" FP-60312102114405_CONN_SMA-MFG 7256,4043.9 r0 top
J34 "60312102114405" FP-60312102114405_CONN_SMA-MFG 7256,2040 r0 top
J35 "571-0100" 571-0100 8101.18,3810 r180 top
J36 "571-0100" 571-0100 8100,1810 r180 top
J37 "571-0500" 571-0500 6990,6600 r270 top
J38 "60312102114405" FP-60312102114405_CONN_SMA-MFG 7210,5790 r0 top
J39 "571-0100" 571-0100 7440,6600 r270 top
L1 "XAL1010-681MEB" XAL1010 1380,5580 r90 top value=680nH
L2 "XAL5030-801MEB" XAL5030 5462.49,3331.01 r90 top value=800nH
L3 "XAL5030-801MEB" XAL5030 5458.59,5413.88 r90 top value=800nH
L4 "XAL5030-801MEB" XAL5030 5454.25,4377.43 r90 top value=800nH
L5 "XAL5030-122MEB" XAL5030 3984.06,2271.13 r90 top value=1.2uH
L6 "XAL6030-182MEB" XAL6030 5496.45,6488.11 r90 top value=1.8uH
Logo1 "Texas Instruments" TI_Stacked_Overlay_Small 1020,290 r0 top
Logo2 "FCC disclaimer" FCC_disclaimer 8410,6240 r90 top
Logo3 "WEEE logo" WEEE_Minimum 8170,5980 r90 top
Logo4 "CAUTION HOT SURFACE" IEC_HotSurface_Medium 310,6380 r270 top
Q1 "EPC7019GC" FP-EPC7019GC_FSMD-G-MFG 1197.5,4690 r270 top
Q2 "EPC7019GC" FP-EPC7019GC_FSMD-G-MFG 1480,4329.05 r270 top
Q3 "EPC7019GC" FP-EPC7019GC_FSMD-G-MFG 1480,4690 r270 top
Q4 "EPC7019GC" FP-EPC7019GC_FSMD-G-MFG 1480,5052.99 r270 top
Q5 "CSD16408Q5" DQH0008A 2845,5560 r180 bottom value=25V
Q6 "FBG04N08ACH" FP-FBG04N08ACH_FSMD-A-MFG 2977.16,4901.02 r90 top
R1 "FC0603E50R0BTBST1" 0603 2750,3890.04 r90 top value=50
R2 "PHT0603Y1002BGT200" 0603 2680,3890.04 r90 top value=10.0k
R3 "CRCW06031M00FKEA" 0603 2361.5,3485 r180 top value=1.00Meg
R4 "RG1608P-333-B-T5" 0603 2610,3890.04 r270 top value=33.0k
R5 "RCS06030000Z0EA" 0603 2030,3733.6 r270 top value=0
R6 "TNPW060310R0BEEA" 0603 2770,3550.04 r270 top value=10.0
R7 "RT0603BRD0740K2L" 0603 2460,3955.89 r270 top value=40.2k
R8 "RCS06030000Z0EA" 0603 2100,3733.6 r90 top value=0
R9 "RG1608P-114-B-T5" 0603 2170,3733.6 r90 top value=110k
R10 "RCS06030000Z0EA" 0603 2380,3955.89 r270 top value=0
R11 "RN73H1JTTD3973F25" 0603 2100,3920.04 r270 top value=397k
R12 "RN73H1JTTD3973F25" 0603 2170,3920.04 r270 top value=397k
R13 "RT0603BRD0749K9L" 0603 2680,3718.09 r90 top value=49.9k
R14 "RN73H1JTTD3973F25" 0603 2030,3920.04 r270 top value=397k
R15 "ERJ-3RQF2R2V" 0603 1165.02,3710 r270 top value=2.20
R16 "RCS06030000Z0EA" 0603 2460,3440.94 r90 top value=0
R17 "RCS06030000Z0EA" 0603 2590,6140 r0 top value=0
R18 "RCS06030000Z0EA" 0603 1970,3580 r270 bottom value=0
R19 "RCS06030000Z0EA" 0603 1970,3580 r90 top value=0
R20 "CRCW06033R30JNEA" 0603 1319.64,4617.01 r180 bottom value=3.3
R21 "RCS06030000Z0EA" 0603 1287.45,4502.01 r90 bottom value=0
R22 "PHT0603Y1002BGT200" 0603 1200,3971.5 r90 top value=10.0k
R23 "KRL6432E-M-R007-F-T1" 2512_WIDE 1660,5917.18 r90 top value=0.007
R24 "RT0603BRD0735K7L" 0603 1860,3610 r180 top value=35.7k
R25 "KRL6432E-M-R007-F-T1" 2512_WIDE 1380,5917.18 r90 top value=0.007
R26 "RT0603BRD0737K4L" 0603 1860,3540 r180 top value=37.4k
R27 "KRL6432E-M-R007-F-T1" 2512_WIDE 1100,5917.18 r90 top value=0.007
R28 "RCS06030000Z0EA" 0603 1603.27,4235 r180 bottom value=0
R29 "RCS06030000Z0EA" 0603 1603.27,4595 r180 bottom value=0
R30 "RCS06030000Z0EA" 0603 1603.27,4960 r180 bottom value=0
R31 "RG1608P-2101-B-T5" 0603 1050,5500 r90 top value=2.10k
R32 "RCS06030000Z0EA" 0603 1491.07,4160 r0 bottom value=0
R33 "RCS06030000Z0EA" 0603 1491.07,4520 r0 bottom value=0
R34 "RCS06030000Z0EA" 0603 1491.07,4880 r0 bottom value=0
R35 "PHT0603Y1002BGT200" 0603 1610,4010 r180 bottom value=10.0k
R36 "RCS06030000Z0EA" 0603 2990,5380 r90 top value=0
R37 "PHT0603Y1002BGT200" 0603 3090,5380 r90 top value=10.0k
R38 "PE2512FKF7W0R062L" 2512_084 3160,5585 r180 bottom value=0.062
R39 "CRCW0603510RJNEA" 0603 2590,2900 r0 top value=510
R40 "CRCW0603510RJNEA" 0603 2590,2660 r0 top value=510
R41 "CRCW0603510RJNEA" 0603 2590,2820 r0 top value=510
R42 "CRCW0603510RJNEA" 0603 2590,2582.26 r0 top value=510
R43 "CRCW0603510RJNEA" 0603 2590,2740 r0 top value=510
R44 "RT0603DRE0756K9L" 0603 1880,2799.57 r90 top value=56.9k
R45 "CRCW0603510RJNEA" 0603 2590,2500 r0 top value=510
R46 "RT0603BRD07118KL" 0603 1740,2800 r90 top value=118k
R47 "CRCW0603510RJNEA" 0603 2590,2430 r0 top value=510
R48 "RT0603BRD0729K4L" 0603 1600,2799.57 r90 top value=29.4k
R49 "TNPW060354K2BEEN" 0603 1530,2610 r270 top value=54.2k
R50 "RT0603BRD073K61L" 0603 1809.16,2799.57 r270 top value=3.61k
R51 "RT0603BRD0728K7L" 0603 1670,2799.57 r270 top value=28.7k
R52 "RN73H1JTTD1113B25" 0603 1530,2799.57 r270 top value=111k
R53 "PHT0603Y1002BGT200" 0603 1570,2430 r180 top value=10.0k
R54 "RCS06030000Z0EA" 0603 1460,2799.57 r270 top value=0
R55 "RT0603BRD0740K2L" 0603 1600,2610 r90 top value=40.2k
R56 "RG1608P-4992-B-T5" 0603 1570,2500 r0 top value=49.9k
R57 "RT0603DRE0765K7L" 0603 1770,2310 r90 top value=65.7k
R58 "RC0603FR-07976KL" 0603 1840,2310 r90 top value=976k
R59 "ERA-3AEB203V" 0603 1910,2310 r90 top value=20k
R60 "RG1608P-132-B-T5" 0603 1700,2308.1 r90 top value=1.30k
R61 "CRCW0603510RJNEA" 0603 2590,2040 r0 top value=510
R62 "RN73H1JTTD3402B25" 0603 1910,2095.55 r90 top value=34k
R63 "CRCW0603510RJNEA" 0603 2590,1960 r0 top value=510
R64 "TNPW060354K2BEEN" 0603 1770,2095.55 r90 top value=54.2k
R65 "CRCW0603510RJNEA" 0603 2590,1880 r0 top value=510
R66 "RT0603BRD0744K2L" 0603 1620,2025.55 r90 top value=44.2k
R67 "RT0603BRD0775KL" 0603 1840,2095.55 r270 top value=75.0k
R68 "PHT0603Y1002BGT200" 0603 1571.99,1745.55 r180 top value=10.0k
R69 "RT0603BRD0740K2L" 0603 1700,2095.55 r270 top value=40.2k
R70 "RT0603BRD0749K3L" 0603 1550,2025.55 r270 top value=49.3k
R71 "RG1608P-4992-B-T5" 0603 1603.49,1866.24 r270 top value=49.9k
R72 "RT0603DRE0765K7L" 0603 1801.99,1635.55 r90 top value=65.7k
R73 "RC0603FR-07976KL" 0603 1731.99,1635.55 r90 top value=976k
R74 "ERA-3AEB203V" 0603 2151.99,1635.55 r270 top value=20k
R75 "ERA-3AEB112V" 0603 2221.99,1635.55 r90 top value=1.1k
R76 "CSRN2010FKR300" 2010 2710,4930 r180 top value=0.3
R77 "RCS06030000Z0EA" 0603 2950,4720 r90 top value=0
R78 "PHT0603Y1002BGT200" 0603 3020,4720 r90 top value=10.0k
R79 "RC0603FR-074R99L" 0603 4511.81,5341.54 r0 bottom value=4.99
R80 "RC0603FR-074R99L" 0603 4511.81,5341.54 r0 top value=4.99
R81 "RC0603FR-074R99L" 0603 4481.81,4281.54 r0 bottom value=4.99
R82 "RC0603FR-074R99L" 0603 4481.81,4281.54 r0 top value=4.99
R83 "RC0603FR-0751KL" 0603 3877.98,5000.82 r270 top value=51.0k
R84 "RC0603FR-0751KL" 0603 3847.98,3940.82 r270 top value=51.0k
R85 "ERA-3AEB3652V" 0603 4308.89,5341.54 r270 top value=36.5k
R86 "ERA-3AEB3652V" 0603 4278.89,4281.54 r270 top value=36.5k
R87 "ERJ-P6WF10R0V" 0805_HV 3764.62,5358.11 r270 top value=10.0
R88 "ERJ-P6WF10R0V" 0805_HV 3734.62,4298.11 r270 top value=10.0
R89 "RT0603BRD0710KL" 0603 4385.39,5341.54 r90 top value=10.0k
R90 "RG1608P-153-B-T5" 0603 4297.74,4957.97 r90 top value=15.0k
R91 "RT0603BRD0712KL" 0603 4178.67,4962.59 r0 top value=12.0k
R92 "RG1608P-153-B-T5" 0603 4267.74,3897.97 r90 top value=15.0k
R93 "RT0603BRD0712KL" 0603 4148.67,3902.59 r0 top value=12.0k
R94 "RT0603BRD0710KL" 0603 4355.39,4281.54 r90 top value=10.0k
R95 "RT0603DRE075K05L" 0603 4370,4960 r90 top value=5.05k
R96 "RT0603DRE075K05L" 0603 4340,3900 r90 top value=5.05k
R97 "RT0603BRD07392RL" 0603 5880,2252.37 r270 top value=392
R98 "FC0603E50R0BTBST1" 0603 5880,2110 r90 top value=50
R99 "FC0603E50R0BTBST1" 0603 5880,2110 r90 bottom value=50
R100 "RC0603FR-074R99L" 0603 4513.24,3226.29 r0 bottom value=4.99
R101 "RC0603FR-074R99L" 0603 4513.24,3226.29 r0 top value=4.99
R102 "RC0603FR-0751KL" 0603 3879.4,2885.57 r270 top value=51.0k
R103 "RCS06030000Z0EA" 0603 5260,2191.77 r0 top value=0
R104 "ERA-3AEB1872V" 0603 4310.32,3226.29 r270 top value=18.7k
R105 "ERJ-P6WF10R0V" 0805_HV 3766.05,3242.86 r270 top value=10.0
R106 "RC0603FR-0751KL" 0603 5880,1964.88 r270 top value=51.0k
R107 "RT0603BRD079K2L" 0603 4303.55,2842.72 r90 top value=9.20k
R108 "RT0603BRD0712KL" 0603 4180.1,2847.34 r0 top value=12.0k
R109 "RT0603BRD0710KL" 0603 4386.82,3226.29 r90 top value=10.0k
R110 "RT0603DRE075K05L" 0603 4380,2842.72 r90 top value=5.05k
R111 "RCS06030000Z0EA" 0603 3780,6350 r90 top value=0
R112 "FC0603E50R0BTBST1" 0603 4450,6210 r0 top value=50
R113 "PHT0603Y1002BGT200" 0603 4310,6210 r0 top value=10.0k
R114 "RT0603BRD073K2L" 0603 4170,6210 r0 top value=3.20k
R115 "ERJ-6ENF1001V" 0805_HV 350,1500 r0 top value=1.00k
R116 "CRCW0805422RFKEA" 0805_HV 870,1500 r0 top value=422
R117 "FC0603E50R0BTBST1" 0603 5842.01,2947.28 r90 top value=50
R118 "FC0603E50R0BTBST1" 0603 5842.01,2947.28 r90 bottom value=50
R119 "FC0603E50R0BTBST1" 0603 5817.73,5032.18 r90 top value=50
R120 "FC0603E50R0BTBST1" 0603 5817.73,5032.18 r90 bottom value=50
R121 "TNPW060350K5BEEA" 0603 5732.72,2984.58 r0 top value=50.5k
R122 "TNPW060350K5BEEA" 0603 5708.43,5069.48 r0 top value=50.5k
R123 "CRCW060338K3FKEA" 0603 5569.5,2854.7 r0 top value=38.3k
R124 "CRCW060338K3FKEA" 0603 5545.21,4939.6 r0 top value=38.3k
R125 "ERA-3AEB2613V" 0603 5734.69,2830.87 r180 top value=261k
R126 "ERA-3AEB2613V" 0603 5710.4,4915.77 r180 top value=261k
R127 "FC0603E50R0BTBST1" 0603 5813.38,3995.73 r90 top value=50
R128 "FC0603E50R0BTBST1" 0603 5813.38,3995.73 r90 bottom value=50
R129 "FC0603E50R0BTBST1" 0603 4363.58,1887.39 r90 top value=50
R130 "FC0603E50R0BTBST1" 0603 4363.58,1887.39 r90 bottom value=50
R131 "TNPW060350K5BEEA" 0603 5704.08,4033.03 r0 top value=50.5k
R132 "TNPW060350K5BEEA" 0603 4254.29,1924.69 r0 top value=50.5k
R133 "CRCW060338K3FKEA" 0603 5540.86,3903.15 r0 top value=38.3k
R134 "CRCW060338K3FKEA" 0603 4091.07,1794.81 r0 top value=38.3k
R135 "ERA-3AEB2613V" 0603 5706.05,3879.32 r180 top value=261k
R136 "RN73H1JTTD3402B25" 0603 4256.26,1770.98 r180 top value=34k
R137 "FC0603E50R0BTBST1" 0603 5909.14,6092.4 r90 top value=50
R138 "FC0603E50R0BTBST1" 0603 5909.14,6092.4 r90 bottom value=50
R139 "RT0603BRD0750KL" 0603 5799.85,6129.7 r0 top value=50k
R140 "CRCW060338K3FKEA" 0603 5653.93,5972.13 r0 top value=38.3k
R141 "RT0603BRD0722K1L" 0603 5801.82,5975.98 r180 top value=22.1k
SW1 "A6TN-1104" FP-A6TN-1104_PTH_SW_7MM50_4MM48-MFG 570,1190 r270 top
SW2 "430182050816" FP-430182050816_SMT_SW_6MM2_6MM2-MFG 390,750 r0 top
SW3 "430182050816" FP-430182050816_SMT_SW_6MM2_6MM2-MFG 1040,750 r0 top
TP1 "OUTA" Keystone5012 1920,3820 r90 top
TP2 "BODE" Keystone5012 2960,3858.54 r0 top
TP3 "VSNS" Keystone5012 2650,4080 r0 top
TP4 "0V8_SYNC" Keystone5012 2260,3360 r0 top
TP5 "BOOT" Keystone5012 1240,3330 r180 top
TP6 "0V8" Keystone5010 2240,5930 r90 top
TP7 "0V8" Keystone5010 1526.06,6496.06 r0 top
TP8 "SW" Keystone5012 570,5520 r90 top
TP9 "CS" Keystone5012 740,5820 r90 top
TP10 "GND" Keystone5011 2478.22,6010 r90 top
TP11 "GND" Keystone5011 3120,4360 r90 top
TP12 "GND" Keystone5011 2628.43,6496.06 r0 top
TP13 "GND" Keystone5011 560,4490 r0 top
TP14 "GND" Keystone5011 3240,3290 r0 top
TP15 "GND" Keystone5011 560,5060 r0 top
TP16 "12V0_SYS" Keystone5010 974,2798.82 r0 top
TP17 "GND" Keystone5011 974,2326.38 r180 top
TP18 "TRANS" Keystone5012 2990,5230 r90 top
TP19 "EN_3V3_VCCO" Keystone5012 2890,2870 r0 top
TP20 "EN_1V2_VCCO" Keystone5012 2890,2390 r0 top
TP21 "EN_2V5_DDR" Keystone5012 2890,2710 r0 top
TP22 "EN_1V2_MEM" Keystone5012 2890,2230 r0 top
TP23 "EN_12V0_SYS" Keystone5012 2890,3030 r0 top
TP24 "EN_DDR_VTT" Keystone5012 2890,2550 r0 top
TP25 "EN__0V80" Keystone5012 2890,2070 r0 top
TP26 "EN_1V5" Keystone5012 2890,1910 r0 top
TP27 "12V_SNS" Keystone5012 2130,2960 r0 top
TP28 "FAULT" Keystone5012 1370,2240 r0 top
TP29 "SYS_START" Keystone5012 1370,1920 r0 top
TP30 "EN_0V92" Keystone5012 2890,1750 r0 top
TP31 "EN_1V5_GTY" Keystone5012 2890,1590 r0 top
TP32 "EN_1V2" Keystone5012 2890,1430 r0 top
TP33 "1V5_GTY" Keystone5010 4715,5343.36 r0 top
TP34 "1V5_GTY" Keystone5010 3030,952.82 r270 top
TP35 "1V5" Keystone5010 4685,4281.54 r0 top
TP36 "1V5" Keystone5010 4029.48,952.82 r270 top
TP37 "1V5_SMON" Keystone5010 5030,976 r270 top
TP38 "OUTS_1V5" Keystone5012 4480,5490 r0 top
TP39 "OUTS_1V5" Keystone5012 4504.17,4433.6 r0 top
TP40 "GND" Keystone5011 3740,4874.21 r0 top
TP41 "GND" Keystone5011 4900,4874.21 r0 top
TP42 "GND" Keystone5011 2580,948.28 r270 top
TP43 "GND" Keystone5011 4580,976 r270 top
TP44 "GND" Keystone5011 3720,3810 r0 top
TP45 "GND" Keystone5011 4920,3814.21 r0 top
TP46 "GND" Keystone5011 3579.48,948.28 r270 top
TP47 "BODE" Keystone5012 5640,2390 r0 top
TP48 "0V92" Keystone5010 4725,3235 r0 top
TP49 "0V92" Keystone5010 6016.12,950 r270 top
TP50 "VTT" Keystone5010 6450,2030 r0 top
TP51 "0V6_VTT" Keystone5010 7030,950 r270 top
TP52 "OUTS_0V92" Keystone5012 4535.59,3378.36 r0 top
TP53 "VTTREF" Keystone5010 5230,2350 r0 top
TP54 "VTTREF" Keystone5010 7550,1260 r0 top
TP55 "GND" Keystone5011 6440,1695 r0 top
TP56 "GND" Keystone5011 7550,820 r0 top
TP57 "GND" Keystone5011 3740,2767.74 r0 top
TP58 "GND" Keystone5011 4940,3430 r0 top
TP59 "GND" Keystone5011 5580,950 r270 top
TP60 "GND" Keystone5011 5475,1690 r0 top
TP61 "GND" Keystone5011 6590,950 r270 top
TP62 "5V0_SYS" Keystone5010 4870,6290 r0 top
TP63 "BODE" Keystone5012 4510,6060 r0 top
TP64 "GND" Keystone5011 4900,5920 r0 top
TP65 "GND" Keystone5011 3740,5920 r0 top
TP66 "1V2" Keystone5010 6288.47,3457.01 r0 top
TP67 "1V2" Keystone5010 7525.09,3260 r0 top
TP68 "1V2_VCCO" Keystone5010 6264.18,5541.92 r0 top
TP69 "1V2_VCCO" Keystone5010 7525,5260 r0 top
TP70 "SW" Keystone5012 5240,5340 r0 top
TP71 "SW" Keystone5012 5250.23,3239.51 r0 top
TP72 "BODE" Keystone5012 5908.08,2777.8 r0 top
TP73 "BODE" Keystone5012 5883.79,4862.7 r0 top
TP74 "GND" Keystone5011 6380.52,2777.8 r0 top
TP75 "GND" Keystone5011 5269.01,2777.8 r0 top
TP76 "GND" Keystone5011 7525.54,2810 r0 top
TP77 "GND" Keystone5011 6380,4862.7 r0 top
TP78 "GND" Keystone5011 5244.72,4862.7 r0 top
TP79 "GND" Keystone5011 7525,4810 r0 top
TP80 "2V5_DDR" Keystone5010 7525.63,2260 r0 top
TP81 "2V5_DDR" Keystone5010 4810.04,2397.13 r0 top
TP82 "1V2_MEM" Keystone5010 6262.44,4507.19 r0 top
TP83 "1V2_MEM" Keystone5010 7525.09,4260 r0 top
TP84 "SW" Keystone5012 5220,4290 r0 top
TP85 "SW" Keystone5012 3760,2180 r0 top
TP86 "BODE" Keystone5012 5879.44,3826.25 r0 top
TP87 "BODE" Keystone5012 4429.65,1717.91 r0 top
TP88 "GND" Keystone5011 6390,3830 r0 top
TP89 "GND" Keystone5011 5240.37,3826.25 r0 top
TP90 "GND" Keystone5011 7524.83,3810 r0 top
TP91 "GND" Keystone5011 4900,1700 r0 top
TP92 "GND" Keystone5011 3740,1700 r0 top
TP93 "GND" Keystone5011 7525.63,1810 r0 top
TP94 "3V3_VCCO" Keystone5010 6345.6,6595.86 r0 top
TP95 "3V3_VCCO" Keystone5010 6990,6025 r90 top
TP96 "SW" Keystone5012 5246.23,6384.63 r0 top
TP97 "BODE" Keystone5012 5975.21,5922.91 r0 top
TP98 "GND" Keystone5011 6428.6,5919.11 r0 top
TP99 "GND" Keystone5011 5250,5920 r0 top
TP100 "GND" Keystone5011 7440,6025 r90 top
U1 "TPS7H5006MPWTSEP" PW0024A-MFG 2380.83,3693.74 r0 top
U3 "TPS7H3014HFT/EM" HFT0022A-C01-MFG 2011.44,2565 r0 top
U4 "TPS7H2221MDCKTSEP" DCK0006A-MFG 2016.44,2800 r180 top
U5 "TPS7H3014HFT/EM" HFT0022A-C01-MFG 2011.32,1866.24 r0 top
U6 "TPS7H2221MDCKTSEP" DCK0006A-MFG 6660,5763.24 r270 top
U7 "TPS7H2221MDCKTSEP" DCK0006A-MFG 3600,1480 r0 top
U8 "TPS7H2221MDCKTSEP" DCK0006A-MFG 2231.99,1248.02 r0 top
U9 "SN54SC6T14MPWTSEP" PW0014A-MFG 2750,4730 r180 top
U10 "TPS7H2221MDCKTSEP" DCK0006A-MFG 6910,5110 r90 top
U11 "TPS7H2221MDCKTSEP" DCK0006A-MFG 5531.47,1480 r0 top
U12 "TPS7H2221MDCKTSEP" DCK0006A-MFG 6900,3080 r90 top
U13 "TPS7H1111MPWPTSEP" PWP0028A-MFG 4099.93,5218.21 r0 top
U14 "TPS7H1111MPWPTSEP" PWP0028A-MFG 4069.93,4158.21 r0 top
U15 "TPS7H1111MPWPTSEP" PWP0028A-MFG 4105.83,3095.16 r0 top
U16 "TPS7H3302MDAPTSEP" DAP0032F-MFG 5627.55,2068.81 r0 top
U17 "TPS73801MDCQPSEP" DCQ0006A-MFG 4200,6450 r90 top
U18 "TPS7H4010MRNPTSEP" RNP0030A-MFG 5732.72,3166.23 r0 top
U19 "TPS7H4010MRNPTSEP" RNP0030A-MFG 5708.43,5251.13 r0 top
U20 "TPS7H4010MRNPTSEP" RNP0030A-MFG 5704.08,4214.68 r0 top
U21 "TPS7H4010MRNPTSEP" RNP0030A-MFG 4254.29,2106.34 r0 top
U22 "TPS7H4010MRNPTSEP" RNP0030A-MFG 5799.85,6311.35 r0 top
ZZ1 "This Assembly Note is for PCB labels only" AssemblyNoteLabel 708.62,7510.83 r0 top
ZZ2 "These assemblies are ESD sensitive, ESD precautions shall be observed." AssemblyNote 1208.62,7401.95 r0 top
ZZ3 "These assemblies must be clean and free from flux and all contaminants. Use of no clean flux is not acceptable." AssemblyNote 1208.62,7313.39 r0 top
ZZ4 "These assemblies must comply with workmanship standards IPC-A-610 Class 2, unless otherwise specified." AssemblyNote 1208.62,7224.84 r0 top

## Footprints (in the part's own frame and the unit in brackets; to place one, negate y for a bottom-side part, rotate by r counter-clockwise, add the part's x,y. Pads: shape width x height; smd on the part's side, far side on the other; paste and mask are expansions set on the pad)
571-0100 [mm] "Deltron Emcon recommended land pattern 2003-10-13"
  rect 2.3x2.3 hole 1.8: 1(-7.65,0)
  round 2.3 hole 1.8: 2(7.65,0)
  silkscreen extent -9.74,-5.47 11.09,4.88, body extent -12.28,-5.48 11.09,4.88, height 12.41
571-0500 [mm] "Deltron Emcon recommended land pattern 2003-10-13"
  rect 2.3x2.3 hole 1.8: 1(-7.65,0)
  round 2.3 hole 1.8: 2(7.65,0)
  silkscreen extent -9.74,-5.47 11.09,4.88, body extent -12.28,-5.48 11.09,4.88, height 12.41
0603 [mm] "0603 from SM-752 data"
  rect 1x0.95 smd: 1(-0.8,0) 2(0.8,0)
  silkscreen extent -1.52,-0.69 1.52,0.69, body extent -0.87,-0.47 0.87,0.47, height 1
0805_HV [mil] "0805 with 30mil clearance between pads"
  rect 50x63 smd: 1(-40,0) 2(40,0)
  silkscreen extent -74,-40 74,40, body extent -43,-29 43,29, height 57
1206 [mm] "1206 from SM-752 data"
  rect 1.3x1.85 smd: 1(-1.45,0) 2(1.45,0)
  silkscreen extent -2.4,-1.21 2.4,1.21, body extent -1.7,-0.9 1.7,0.9, height 1.35
1206_180 [mm] "1206_180"
  rect 1.1x1.6 smd: 1(-1.7,0) 2(1.7,0)
  silkscreen extent -0.9,-1 0.9,1, body extent -1.75,-0.95 1.75,0.95, height 1.8
1210_220 [mm] "1210"
  rect 1.3x2.7 smd: 1(-1.45,0) 2(1.45,0)
  silkscreen extent -2.32,-1.57 2.32,1.57, body extent -1.7,-1.35 1.7,1.35, height 2.2
1210_270 [mm] "1210"
  rect 1.3x2.7 smd: 1(-1.45,0) 2(1.45,0)
  silkscreen extent -2.32,-1.57 2.32,1.57, body extent -1.7,-1.35 1.7,1.35, height 2.7
1210_280 [mm] "SMD, 2-Leads, Body 3.6x2.8mm, Height 2.8mm"
  rect 1.1x2.2 smd: 1(-1.65,0) 2(1.65,0)
  silkscreen extent -0.84,-1.4 0.84,1.4, body extent -1.8,-1.4 1.8,1.4, height 2.8
2010 [mm] "Chip Capacitor, Body 5.08x2.54mm, IPC Medium Density"
  rect 1.6x2.7 smd: 1(-2.3,0) 2(2.3,0)
  silkscreen extent -3.42,-1.65 3.42,1.65, body extent -2.73,-1.45 2.73,1.45, height 1.66
2512_084 [mm] "Chip Resistor, Body 6.3x3.2mm"
  rect 1.3x3.4 smd: 1(-2.95,0) 2(2.95,0)
  silkscreen extent -1.9,-1.6 1.9,1.6, body extent -3.22,-1.67 3.22,1.67, height 0.84
2512_WIDE [mm] "Ohmite recommended land pattern"
  rect 1x6.6 smd: 1(-1.6,0) 2(1.6,0)
  silkscreen extent -0.82,-3.32 0.82,3.35, body extent -1.65,-3.25 1.65,3.25, height 0.7
3216-18 [mm] "Based on AVX recommendation in http://www.avx.com/download/software/literature/AVX-Footprint-Library.pdf"
  rrect7% 1.4x1.8 smd: 1(-1.3,0) 2(1.3,0)
  silkscreen extent -1.9,-1.12 0.8,1.12, body extent -1.7,-0.9 1.7,0.9, height 1.82
3528-21 [mm] "Medium Density IPC, based on Kemet datasheet 2016-10-20"
  rrect6% 1.8x2.23 smd: 1(-1.46,0) 2(1.46,0)
  silkscreen extent -2.29,-1.5 0.76,1.5, body extent -1.85,-1.5 1.85,1.5, height 2.12
7343-31 [mm] "Medium Density based on Kemet T495 dimensions"
  rect 2.55x2.45 smd: 1(-3.025,0) 2(3.025,0)
  silkscreen extent -4.56,-2.3 3.8,2.3, body extent -3.8,-2.3 3.8,2.3, height 3.1
APHHS1005_Green [mm] "SMD, 2-Leads, Body 1x0.5mm"
  rrect20% 0.7x0.5 smd: 1(-0.45,0) 2(0.45,0)
  silkscreen extent -0.8,-0.65 1.2,0.65, body extent -0.5,-0.25 0.5,0.25, height 0.5
AssemblyNote [mil] "Assembly Note"
AssemblyNoteLabel [mil] "Assembly Note for PCB Labels"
